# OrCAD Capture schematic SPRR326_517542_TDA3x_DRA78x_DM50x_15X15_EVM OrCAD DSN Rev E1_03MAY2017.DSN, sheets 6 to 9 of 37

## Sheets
6 SH07 - DDR3: size C; rev: E
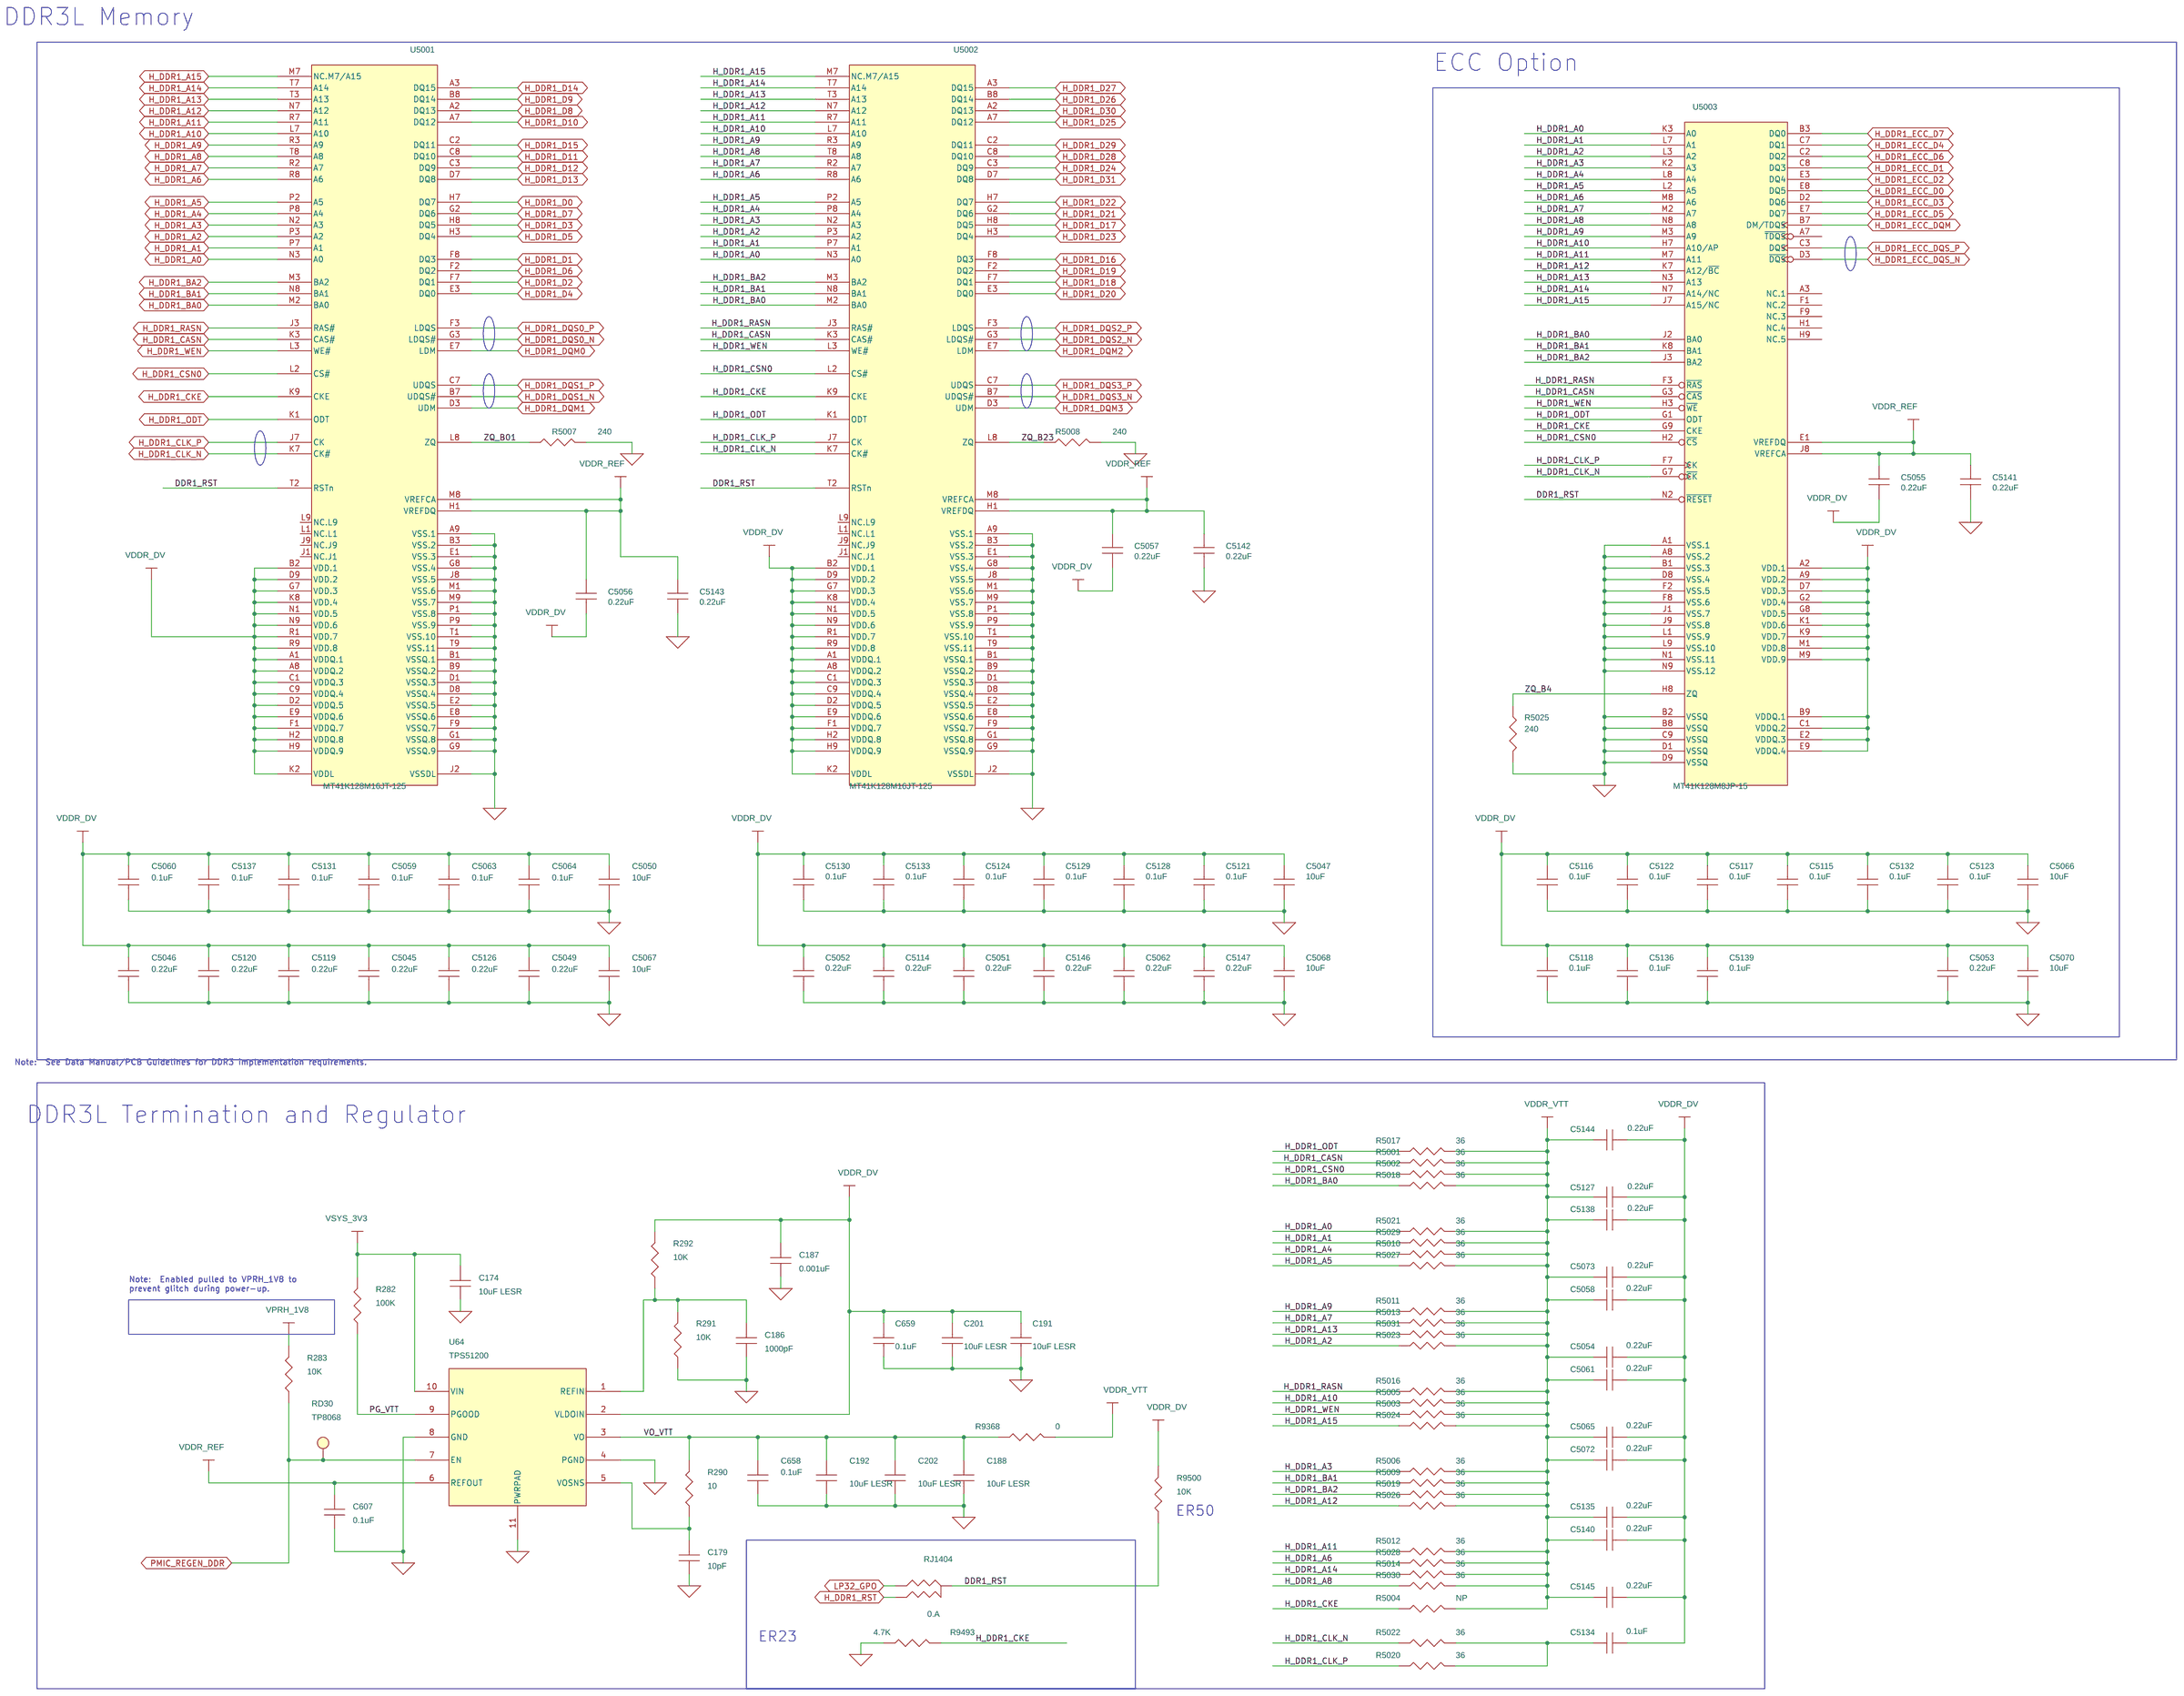
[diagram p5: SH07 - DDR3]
7 SH08 - VISIBILITY: size C; rev: D
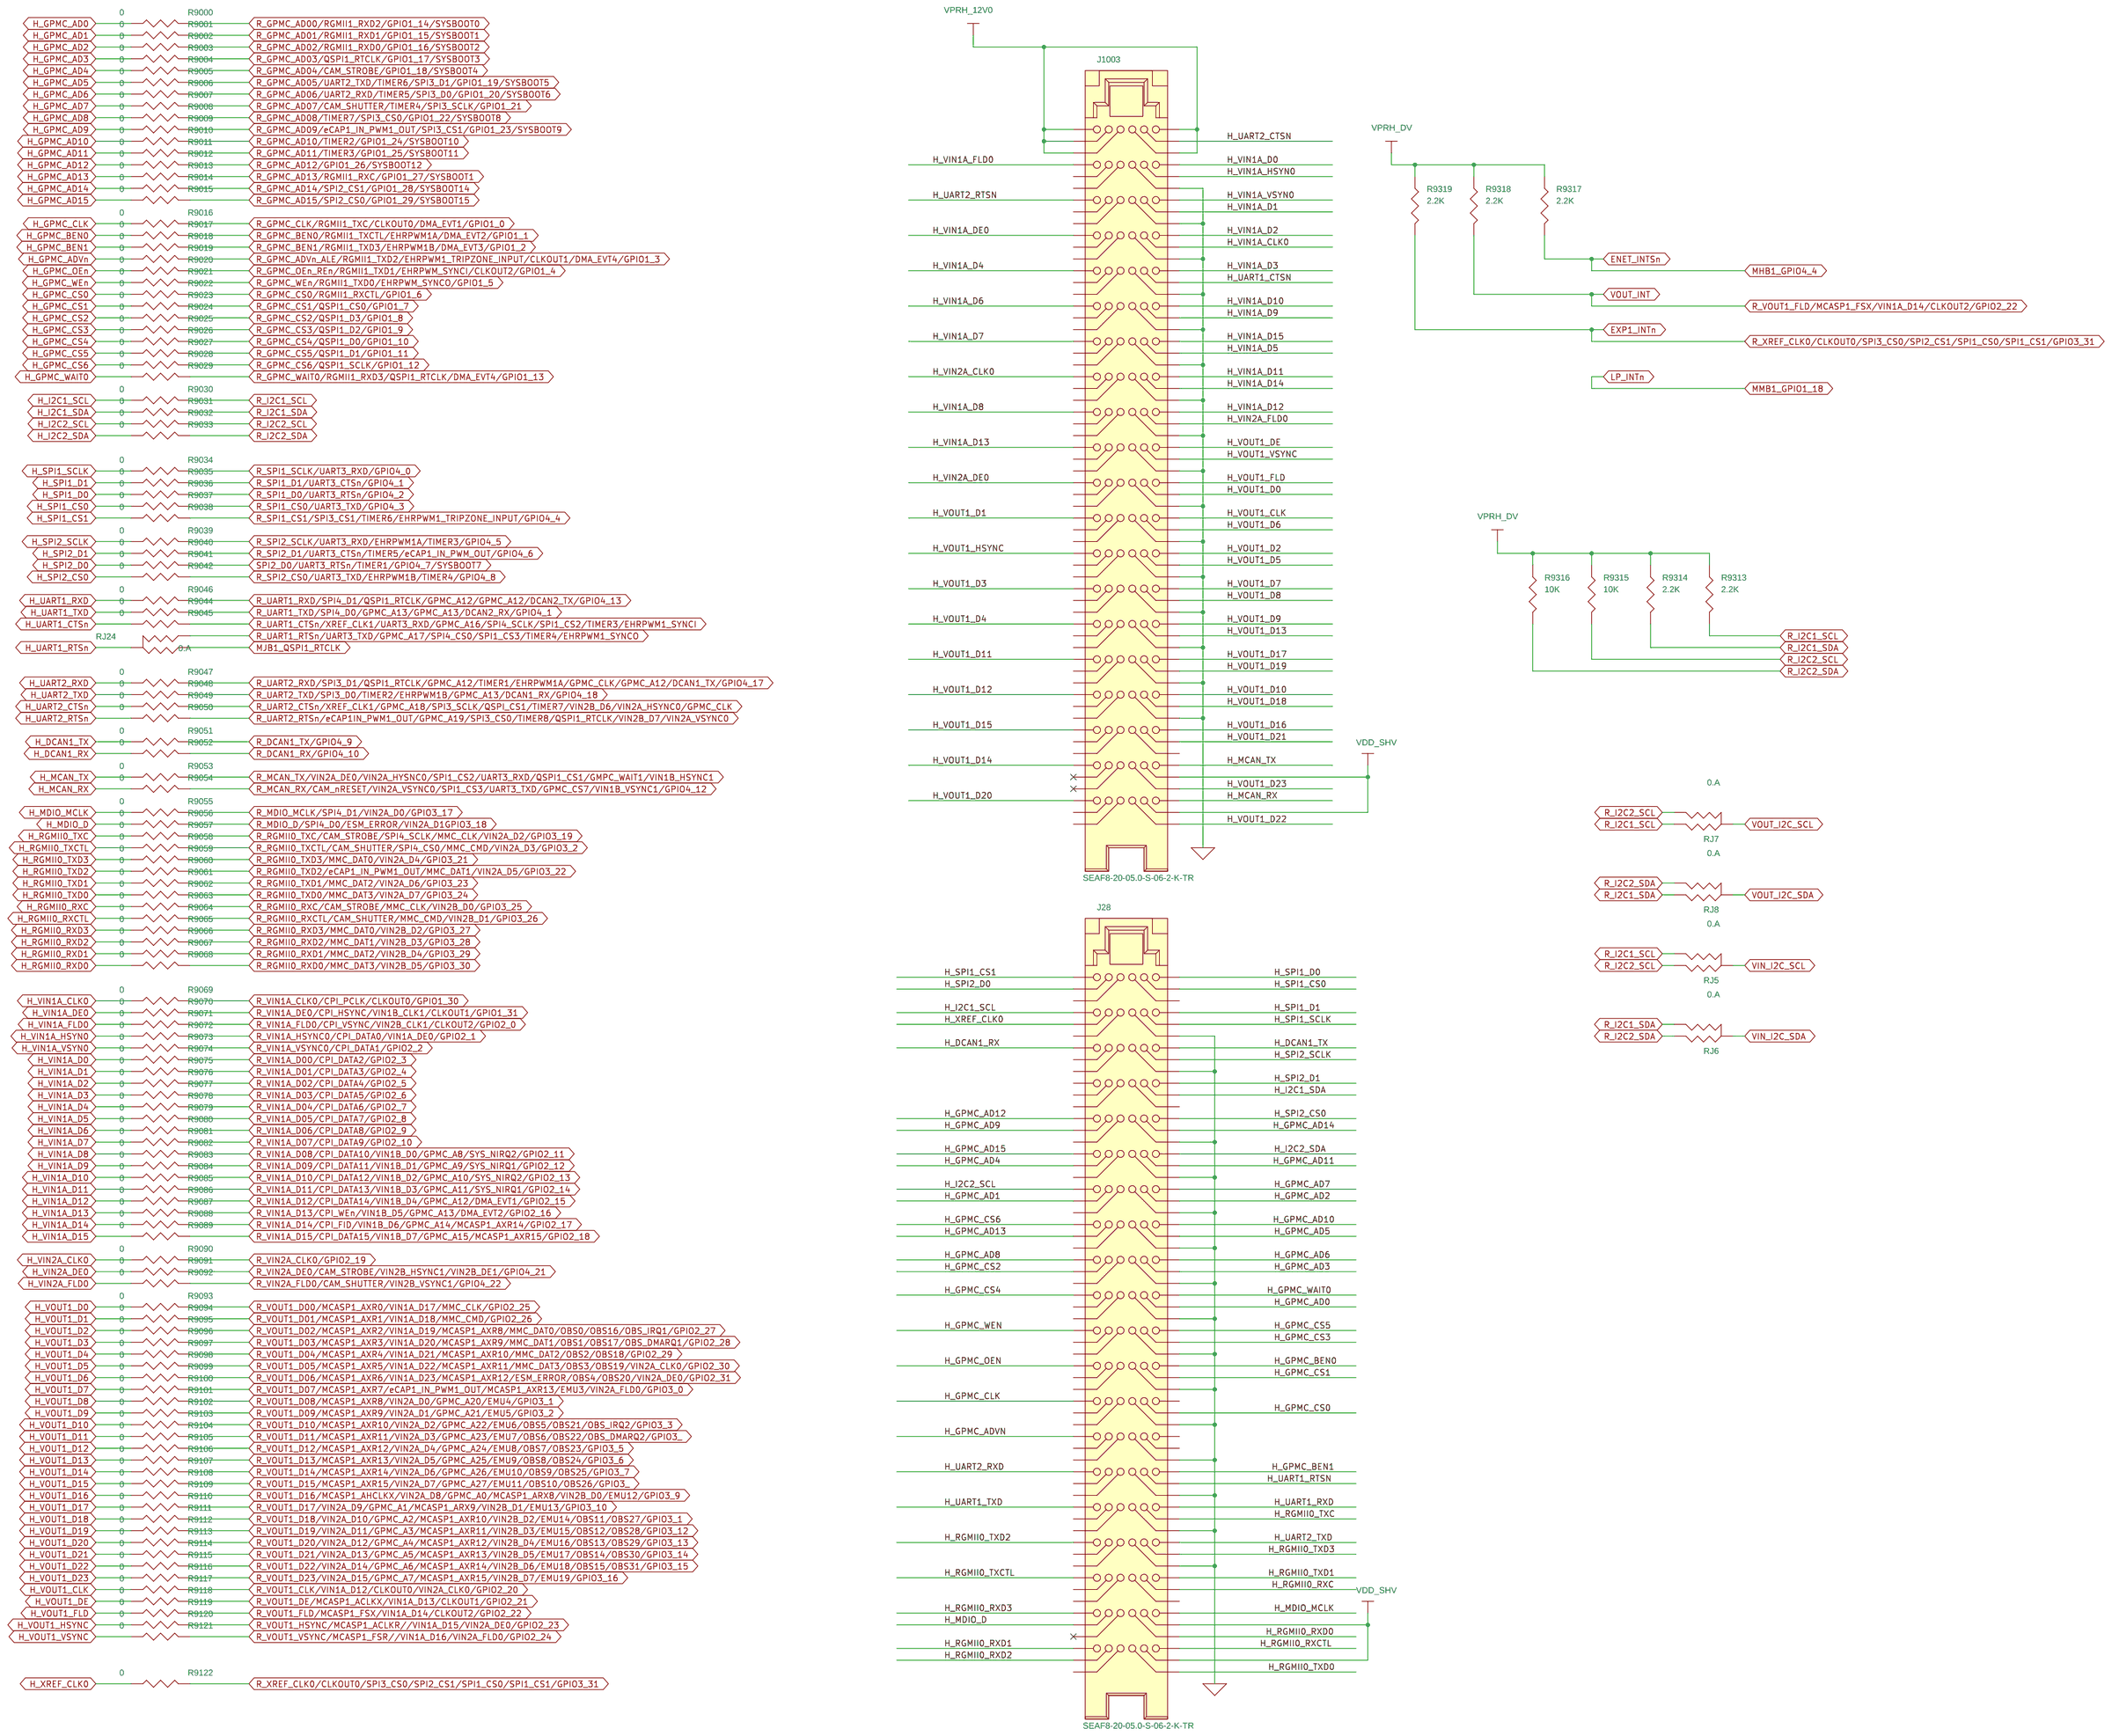
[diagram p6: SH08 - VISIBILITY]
8 SH10 - I2C EXPANDER: size C
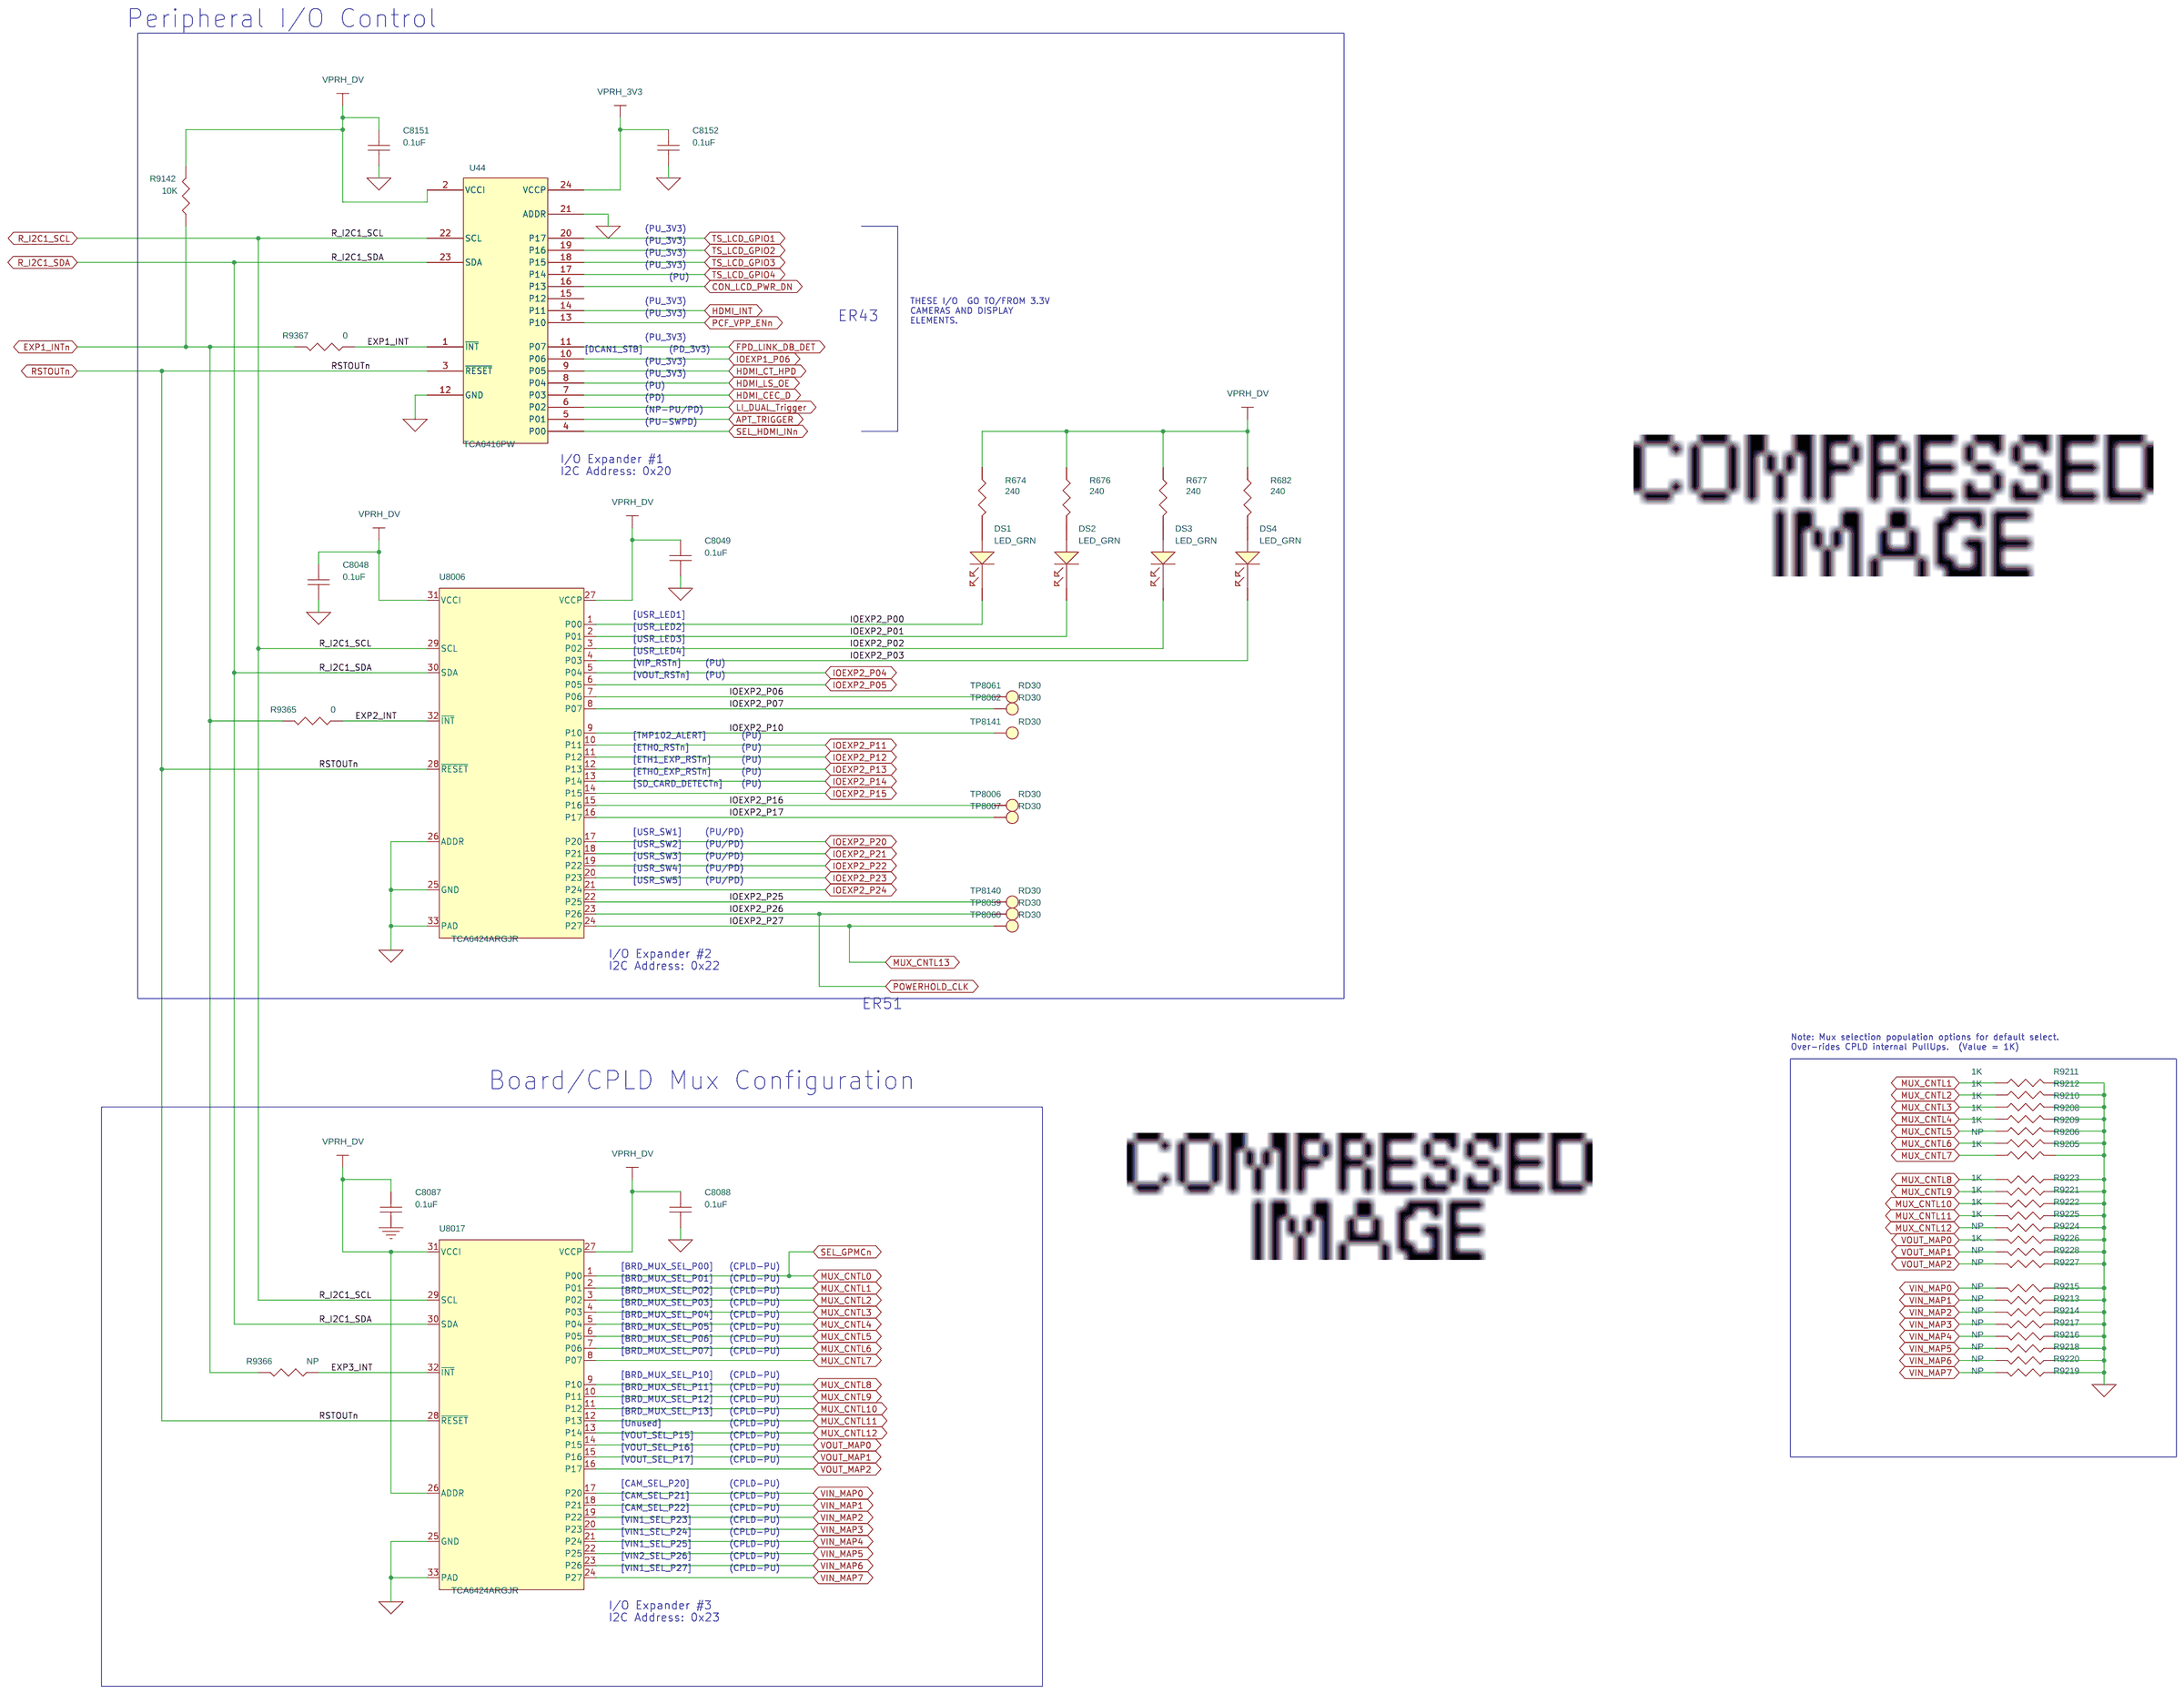
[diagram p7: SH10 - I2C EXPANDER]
9 SH15 - MEM NONVOLATILE: size C; rev: D
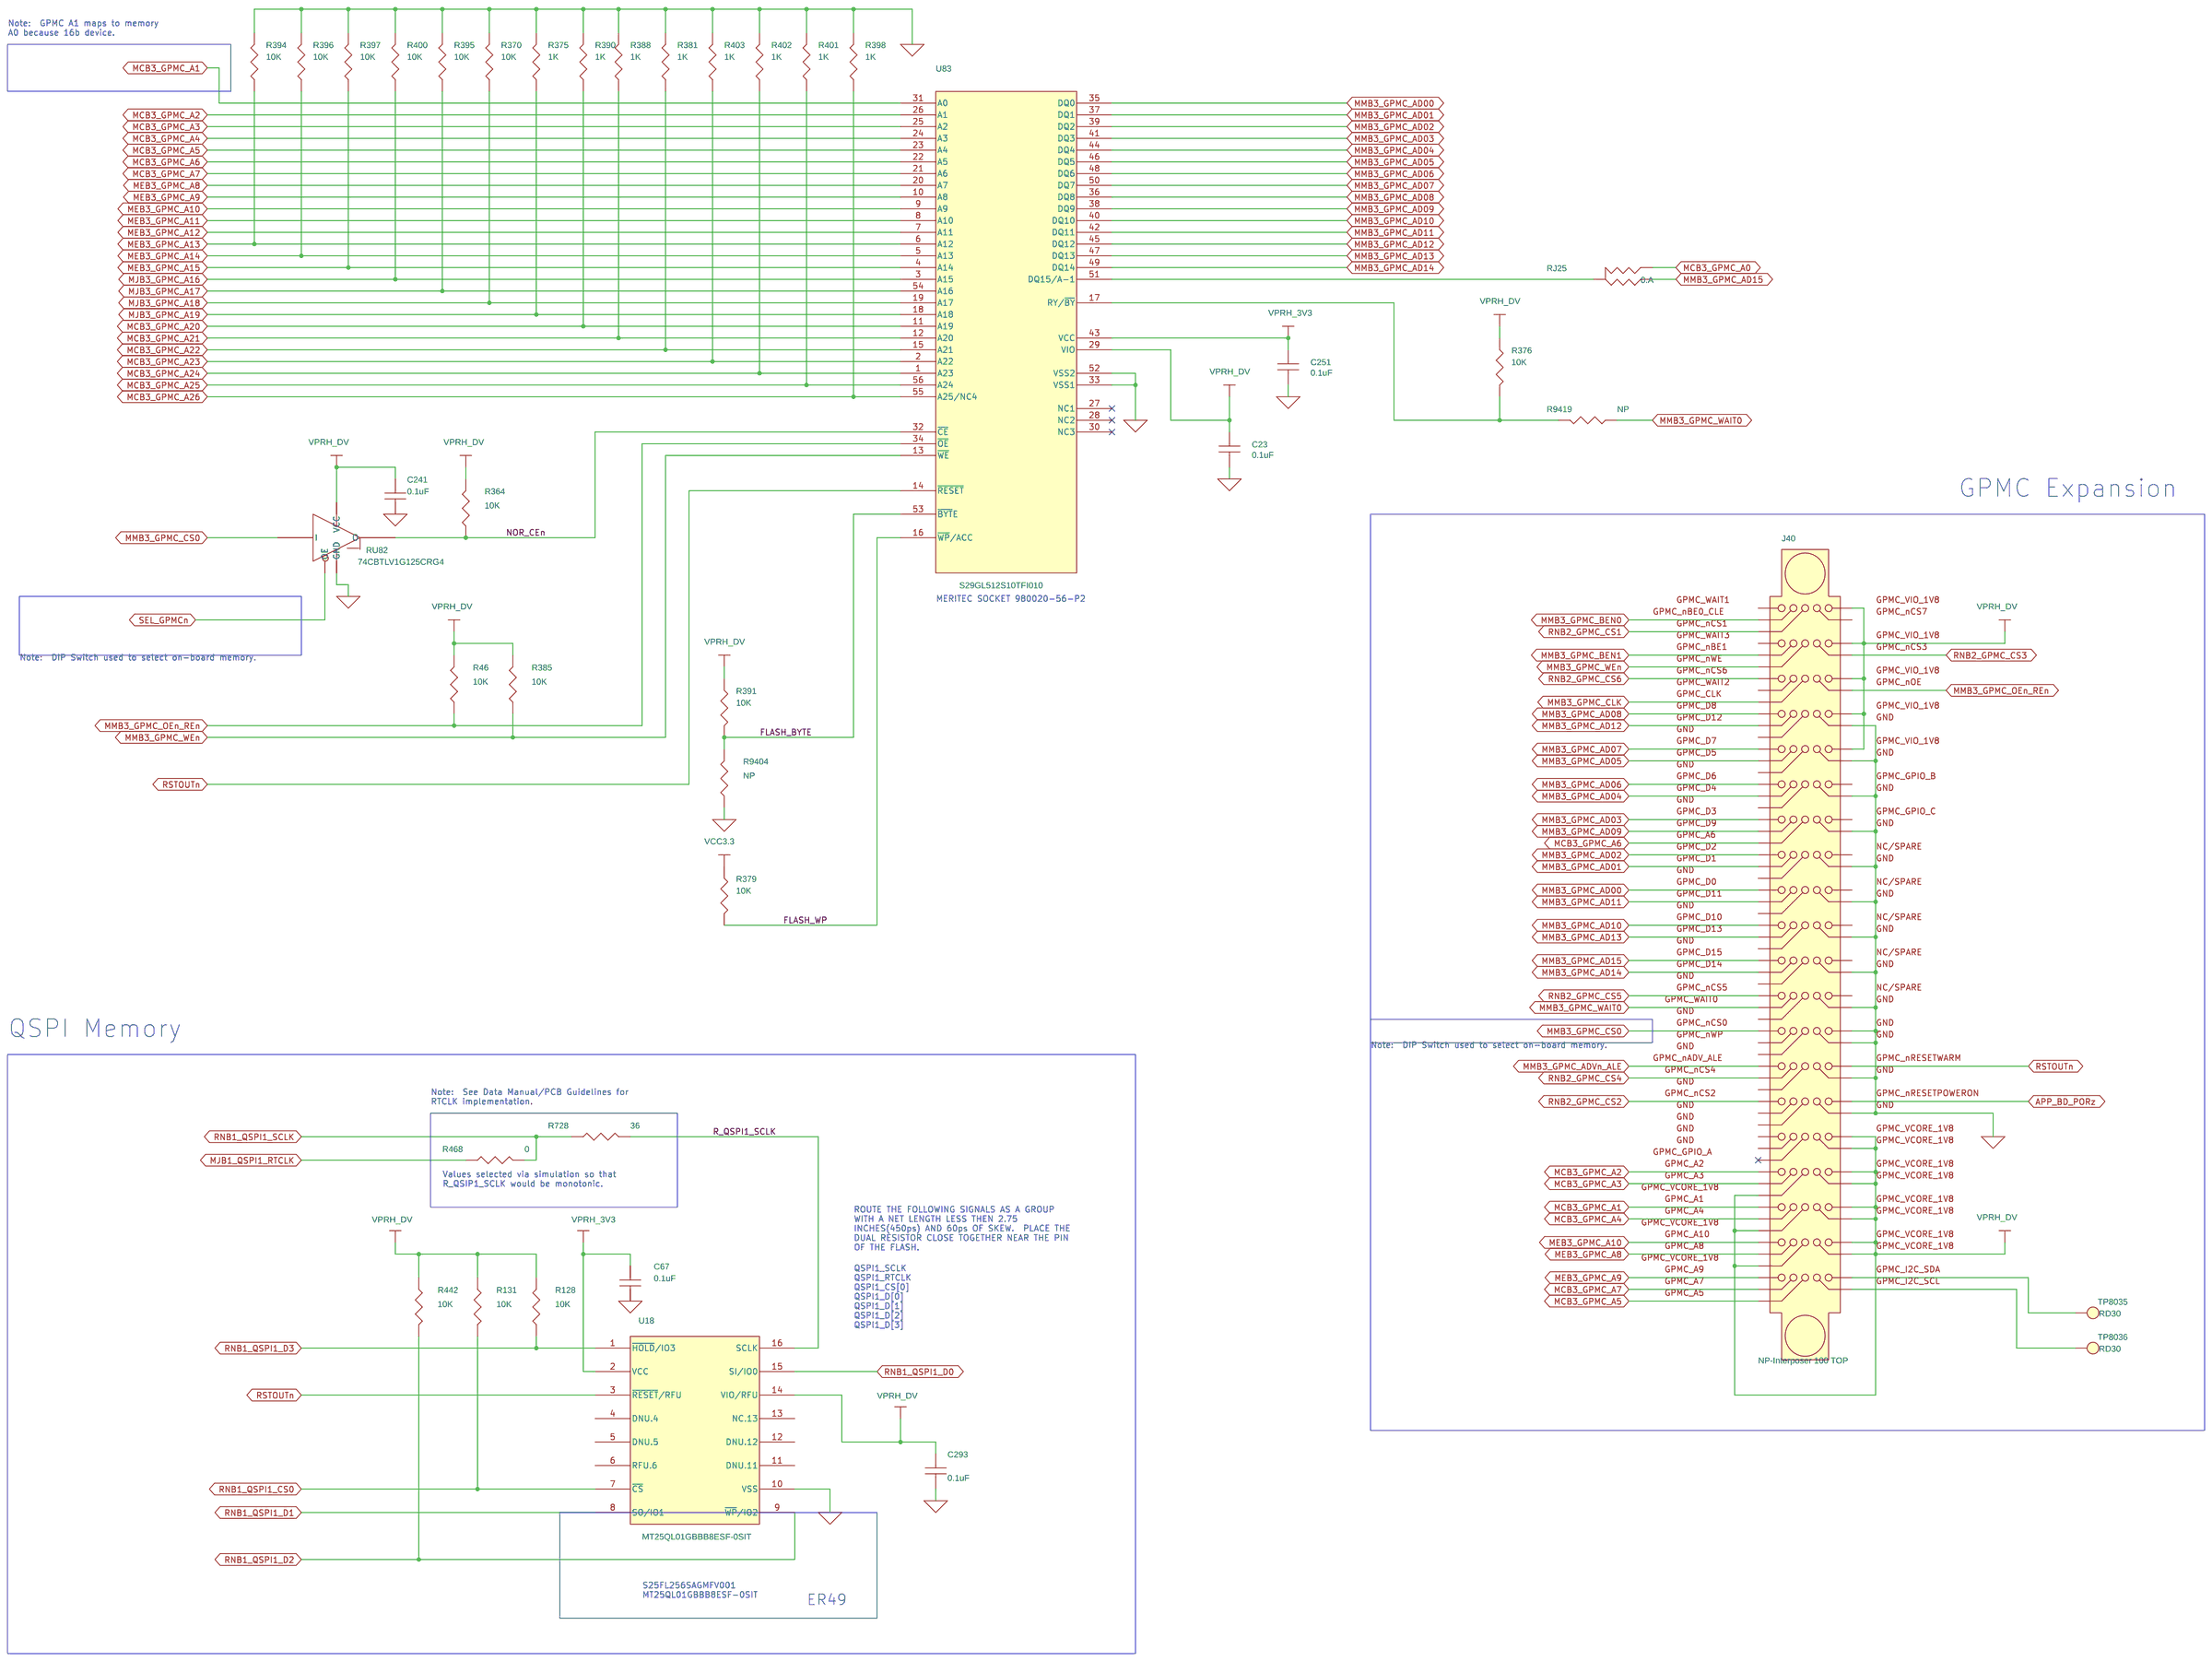
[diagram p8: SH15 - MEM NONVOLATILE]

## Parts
sheet SH07 - DDR3
C174  10uF LESR  [C1206-40X70]
C179  10pF  [c402-25]
C186  1000pF  [c402-25]
C187  0.001uF  [c402-25]
C188  10uF LESR  [C1206-40X70]
C191  10uF LESR  [C1206-40X70]
C192  10uF LESR  [C1206-40X70]
C201  10uF LESR  [C1206-40X70]
C202  10uF LESR  [C1206-40X70]
C607  0.1uF  [c402-25]
C658  0.1uF  [c402-25]
C659  0.1uF  [c402-25]
C5045  0.22uF  [c603-35x45]
C5046  0.22uF  [c603-35x45]
C5047  10uF  [c805-35x60]
C5049  0.22uF  [c603-35x45]
C5050  10uF  [c805-35x60]
C5051  0.22uF  [c603-35x45]
C5052  0.22uF  [c603-35x45]
C5053  0.22uF  [c603-35x45]
C5054  0.22uF  [c603-35x45]
C5055  0.22uF  [c603-35x45]
C5056  0.22uF  [c603-35x45]
C5057  0.22uF  [c603-35x45]
C5058  0.22uF  [c603-35x45]
C5059  0.1uF  [c402-25rd]
C5060  0.1uF  [c402-25rd]
C5061  0.22uF  [c603-35x45]
C5062  0.22uF  [c603-35x45]
C5063  0.1uF  [c402-25rd]
C5064  0.1uF  [c402-25rd]
C5065  0.22uF  [c603-35x45]
C5066  10uF  [c805-35x60]
C5067  10uF  [c805-35x60]
C5068  10uF  [c805-35x60]
C5070  10uF  [c805-35x60]
C5072  0.22uF  [c603-35x45]
C5073  0.22uF  [c603-35x45]
C5114  0.22uF  [c603-35x45]
C5115  0.1uF  [c402-25rd]
C5116  0.1uF  [c402-25rd]
C5117  0.1uF  [c402-25rd]
C5118  0.1uF  [c402-25rd]
C5119  0.22uF  [c603-35x45]
C5120  0.22uF  [c603-35x45]
C5121  0.1uF  [c402-25rd]
C5122  0.1uF  [c402-25rd]
C5123  0.1uF  [c402-25rd]
C5124  0.1uF  [c402-25rd]
C5126  0.22uF  [c603-35x45]
C5127  0.22uF  [c603-35x45]
C5128  0.1uF  [c402-25rd]
C5129  0.1uF  [c402-25rd]
C5130  0.1uF  [c402-25rd]
C5131  0.1uF  [c402-25rd]
C5132  0.1uF  [c402-25rd]
C5133  0.1uF  [c402-25rd]
C5134  0.1uF  [c402-25rd]
C5135  0.22uF  [c603-35x45]
C5136  0.1uF  [c402-25rd]
C5137  0.1uF  [c402-25rd]
C5138  0.22uF  [c603-35x45]
C5139  0.1uF  [c402-25rd]
C5140  0.22uF  [c603-35x45]
C5141  0.22uF  [c603-35x45]
C5142  0.22uF  [c603-35x45]
C5143  0.22uF  [c603-35x45]
C5144  0.22uF  [c603-35x45]
C5145  0.22uF  [c603-35x45]
C5146  0.22uF  [c603-35x45]
C5147  0.22uF  [c603-35x45]
R282  100K  [r402-25]
R283  10K  [r402-25]
R290  10  [r402-25]
R291  10K  [r402-25]
R292  10K  [r402-25]
R5001  36  [r402-25]
R5002  36  [r402-25]
R5003  36  [r402-25]
R5004  NP  [r402-25]
R5005  36  [r402-25]
R5006  36  [r402-25]
R5007  240  [r402-25]
R5008  240  [r402-25]
R5009  36  [r402-25]
R5010  36  [r402-25]
R5011  36  [r402-25]
R5012  36  [r402-25]
R5013  36  [r402-25]
R5014  36  [r402-25]
R5016  36  [r402-25]
R5017  36  [r402-25]
R5018  36  [r402-25]
R5019  36  [r402-25]
R5020  36  [r402-25]
R5021  36  [r402-25]
R5022  36  [r402-25]
R5023  36  [r402-25]
R5024  36  [r402-25]
R5025  240  [r402-25]
R5026  36  [r402-25]
R5027  36  [r402-25]
R5028  36  [r402-25]
R5029  36  [r402-25]
R5030  36  [r402-25]
R5031  36  [r402-25]
R9368  0  [r603-35x45]
R9493  4.7K  [r402-25]
R9500  10K  [r402-25]
RJ1404  0.A  [JMP402-25]
TP8068  RD30  [tp-30RD13]
U64  TPS51200  [drc10-11x33]
U5001  MT41K128M16JT-125  [intbga6x16-p8-re-pkg]
U5002  MT41K128M16JT-125  [intbga6x16-p8-re-pkg]
U5003  MT41K128M8JP-15  [intbga6x13-p8-ra-pkg]
sheet SH08 - VISIBILITY
J28  SEAF8-20-05.0-S-06-2-K-TR  [ti-jfs_seaf8-6x20pts_01]
J1003  SEAF8-20-05.0-S-06-2-K-TR  [ti-jfs_seaf8-6x20pts_01]
R9000  0  [r201-6p6spc]
R9001  0  [r201-6p6spc]
R9002  0  [r201-6p6spc]
R9003  0  [r201-6p6spc]
R9004  0  [r201-6p6spc]
R9005  0  [r201-6p6spc]
R9006  0  [r201-6p6spc]
R9007  0  [r201-6p6spc]
R9008  0  [r201-6p6spc]
R9009  0  [r201-6p6spc]
R9010  0  [r201-6p6spc]
R9011  0  [r201-6p6spc]
R9012  0  [r201-6p6spc]
R9013  0  [r201-6p6spc]
R9014  0  [r201-6p6spc]
R9015  0  [r201-6p6spc]
R9016  0  [r201-6p6spc]
R9017  0  [r201-6p6spc]
R9018  0  [r201-6p6spc]
R9019  0  [r201-6p6spc]
R9020  0  [r201-6p6spc]
R9021  0  [r201-6p6spc]
R9022  0  [r201-6p6spc]
R9023  0  [r201-6p6spc]
R9024  0  [r201-6p6spc]
R9025  0  [r201-6p6spc]
R9026  0  [r201-6p6spc]
R9027  0  [r201-6p6spc]
R9028  0  [r201-6p6spc]
R9029  0  [r201-6p6spc]
R9030  0  [r201-6p6spc]
R9031  0  [r201-6p6spc]
R9032  0  [r201-6p6spc]
R9033  0  [r201-6p6spc]
R9034  0  [r201-6p6spc]
R9035  0  [r201-6p6spc]
R9036  0  [r201-6p6spc]
R9037  0  [r201-6p6spc]
R9038  0  [r201-6p6spc]
R9039  0  [r201-6p6spc]
R9040  0  [r201-6p6spc]
R9041  0  [r201-6p6spc]
R9042  0  [r201-6p6spc]
R9044  0  [r201-6p6spc]
R9045  0  [r201-6p6spc]
R9046  0  [r201-6p6spc]
R9047  0  [r201-6p6spc]
R9048  0  [r201-6p6spc]
R9049  0  [r201-6p6spc]
R9050  0  [r201-6p6spc]
R9051  0  [r201-6p6spc]
R9052  0  [r201-6p6spc]
R9053  0  [r201-6p6spc]
R9054  0  [r201-6p6spc]
R9055  0  [r201-6p6spc]
R9056  0  [r201-6p6spc]
R9057  0  [r201-6p6spc]
R9058  0  [r201-6p6spc]
R9059  0  [r201-6p6spc]
R9060  0  [r201-6p6spc]
R9061  0  [r201-6p6spc]
R9062  0  [r201-6p6spc]
R9063  0  [r201-6p6spc]
R9064  0  [r201-6p6spc]
R9065  0  [r201-6p6spc]
R9066  0  [r201-6p6spc]
R9067  0  [r201-6p6spc]
R9068  0  [r201-6p6spc]
R9069  0  [r201-6p6spc]
R9070  0  [r201-6p6spc]
R9071  0  [r201-6p6spc]
R9072  0  [r201-6p6spc]
R9073  0  [r201-6p6spc]
R9074  0  [r201-6p6spc]
R9075  0  [r201-6p6spc]
R9076  0  [r201-6p6spc]
R9077  0  [r201-6p6spc]
R9078  0  [r201-6p6spc]
R9079  0  [r201-6p6spc]
R9080  0  [r201-6p6spc]
R9081  0  [r201-6p6spc]
R9082  0  [r201-6p6spc]
R9083  0  [r201-6p6spc]
R9084  0  [r201-6p6spc]
R9085  0  [r201-6p6spc]
R9086  0  [r201-6p6spc]
R9087  0  [r201-6p6spc]
R9088  0  [r201-6p6spc]
R9089  0  [r201-6p6spc]
R9090  0  [r201-6p6spc]
R9091  0  [r201-6p6spc]
R9092  0  [r201-6p6spc]
R9093  0  [r201-6p6spc]
R9094  0  [r201-6p6spc]
R9095  0  [r201-6p6spc]
R9096  0  [r201-6p6spc]
R9097  0  [r201-6p6spc]
R9098  0  [r201-6p6spc]
R9099  0  [r201-6p6spc]
R9100  0  [r201-6p6spc]
R9101  0  [r201-6p6spc]
R9102  0  [r201-6p6spc]
R9103  0  [r201-6p6spc]
R9104  0  [r201-6p6spc]
R9105  0  [r201-6p6spc]
R9106  0  [r201-6p6spc]
R9107  0  [r201-6p6spc]
R9108  0  [r201-6p6spc]
R9109  0  [r201-6p6spc]
R9110  0  [r201-6p6spc]
R9111  0  [r201-6p6spc]
R9112  0  [r201-6p6spc]
R9113  0  [r201-6p6spc]
R9114  0  [r201-6p6spc]
R9115  0  [r201-6p6spc]
R9116  0  [r201-6p6spc]
R9117  0  [r201-6p6spc]
R9118  0  [r201-6p6spc]
R9119  0  [r201-6p6spc]
R9120  0  [r201-6p6spc]
R9121  0  [r201-6p6spc]
R9122  0  [r201-6p6spc]
R9313  2.2K  [r402-25]
R9314  2.2K  [r402-25]
R9315  10K  [r402-25]
R9316  10K  [r402-25]
R9317  2.2K  [r402-25]
R9318  2.2K  [r402-25]
R9319  2.2K  [r402-25]
RJ5  0.A  [JMP402-25]
RJ6  0.A  [JMP402-25]
RJ7  0.A  [JMP402-25]
RJ8  0.A  [JMP402-25]
RJ24  0.A  [JMP402-25]
sheet SH10 - I2C EXPANDER
C8048  0.1uF  [c402-25]
C8049  0.1uF  [c402-25]
C8087  0.1uF  [c402-25]
C8088  0.1uF  [c402-25]
C8151  0.1uF  [c402-25]
C8152  0.1uF  [c402-25]
DS1  LED_GRN  [led1206-59x59]
DS2  LED_GRN  [led1206-59x59]
DS3  LED_GRN  [led1206-59x59]
DS4  LED_GRN  [led1206-59x59]
R674  240  [r402-25]
R676  240  [r402-25]
R677  240  [r402-25]
R682  240  [r402-25]
R9142  10K  [r402-25]
R9205  1K  [r402-25]
R9206  NP  [r402-25]
R9208  1K  [r402-25]
R9209  1K  [r402-25]
R9210  1K  [r402-25]
R9211  1K  [r402-25]
R9212  1K  [r402-25]
R9213  NP  [r402-25]
R9214  NP  [r402-25]
R9215  NP  [r402-25]
R9216  NP  [r402-25]
R9217  NP  [r402-25]
R9218  NP  [r402-25]
R9219  NP  [r402-25]
R9220  NP  [r402-25]
R9221  1K  [r402-25]
R9222  1K  [r402-25]
R9223  1K  [r402-25]
R9224  NP  [r402-25]
R9225  1K  [r402-25]
R9226  1K  [r402-25]
R9227  NP  [r402-25]
R9228  NP  [r402-25]
R9365  0  [r402-25]
R9366  NP  [r402-25]
R9367  0  [r402-25]
TP8006  RD30  [tp-30RD13]
TP8007  RD30  [tp-30RD13]
TP8059  RD30  [tp-30RD13]
TP8060  RD30  [tp-30RD13]
TP8061  RD30  [tp-30RD13]
TP8062  RD30  [tp-30RD13]
TP8140  RD30  [tp-30RD13]
TP8141  RD30  [tp-30RD13]
U44  TCA6416PW  [pw24-14x70]
U8006  TCA6424ARGJR  [cis_pvqfn-n32_01]
U8017  TCA6424ARGJR  [cis_pvqfn-n32_01]
sheet SH15 - MEM NONVOLATILE
C23  0.1uF  [c402-25]
C67  0.1uF  [c402-25]
C241  0.1uF  [c402-25]
C251  0.1uF  [c402-25]
C293  0.1uF  [c402-25]
J40  NP-Interposer 100 TOP  [ti-JMS_7170-020-GPMC_01]
R46  10K  [r402-25]
R128  10K  [r402-25]
R131  10K  [r402-25]
R364  10K  [r402-25]
R370  10K  [r402-25]
R375  1K  [r402-25]
R376  10K  [r402-25]
R379  10K  [r402-25]
R381  1K  [r402-25]
R385  10K  [r402-25]
R388  1K  [r402-25]
R390  1K  [r402-25]
R391  10K  [r402-25]
R394  10K  [r402-25]
R395  10K  [r402-25]
R396  10K  [r402-25]
R397  10K  [r402-25]
R398  1K  [r402-25]
R400  10K  [r402-25]
R401  1K  [r402-25]
R402  1K  [r402-25]
R403  1K  [r402-25]
R442  10K  [r402-25]
R468  0  [r402-25]
R728  36  [r402-25]
R9404  NP  [r402-25]
R9419  NP  [r402-25]
RJ25  0.A  [JMP402-25]
RU82  74CBTLV1G125CRG4  [dck-5]
TP8035  RD30  [tp-30RD13]
TP8036  RD30  [tp-30RD13]
U18  MT25QL01GBBB8ESF-0SIT  [so16-25x75-300]
U83  S29GL512S10TFI010  [x-s_tsop56_01]

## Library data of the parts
C174 C188 C191 C192 C201 C202 = CAP_NP: Part #: 101497-0101R
C179 = CAP_NP: Part #: 101782-1104R
C186 C187 = CAP_NP: Part #: 102058-1102R
C67 C293 C607 C658 C659 = CAP_NP: Part #: 104446-1100R
C5045 C5046 C5049 C5051-C5058 C5061 C5062 C5065 C5072 C5073 C5114 C5119 C5120 C5126 C5127 C5135 C5138 C5140-C5147 = CAP_AM_0603_0.22uf_x8l_16v_10_X: Part #: 103885-1220R
C5047 C5050 C5066-C5068 C5070 = CAP_AM_0805_10uf_x7r_10v_10_X: Part #: 104447-0101R
C5059 C5060 C5063 C5064 C5115-C5118 C5121-C5124 C5128-C5134 C5136 C5137 C5139 = CAP_AM_0402_0.1uf_x7r_16v_10%_X: Part #: 104446-1100R
R282 = R: Part #: 101370-1004R
R46 R283 R292 R364 R370 R376 R379 R385 R391 R394-R397 R400 R9315 R9316 R9500 = R: Part #: 101370-1003R
R290 = R: Part #: 101370-1000R
R291 = R: Part #: 102145-1003R
R5001-R5003 R5005 R5006 R5009-R5014 R5016-R5024 R5026-R5031 = RES_0402_49.9_1%_0.063W_X: Part #: 102145-3600R
R5004 = RES_0402_49.9_1%_0.063W_X: Part #: R0402-NOPOP
R5007 R5008 = R_0: Part #: 102145-2401R; SD PCB Footprint: EIA0402
R5025 = R: Part #: 102145-2401R
R9368 = R: Part #: 100687-0001R
R9493 = R: Part #: 101370-4702R
RJ5-RJ8 RJ24 RJ25 RJ1404 = RJUMP3: Part #: 101370-0001R
TP8006 TP8007 TP8035 TP8036 TP8059-TP8062 TP8068 TP8140 TP8141 = TESTPOINT: Part #: TP-30RD13-NO-POP
U64 = TPS51200: Part #: 103316-0001R
U5001 U5002 = DDR3_96BALL_X16_0: Part #: 104254-0012R
U5003 = EDJ1108DBSE_1: Part #: 104177-0125R
J28 J1003 = SEAF8-20-05.0-S-06-2-K-TR: Part #: 104455-2006R
R9000-R9042 R9044-R9122 = R_1: Part #: 103158-0001R
R9313 R9314 R9317-R9319 = R: Part #: 101370-2202R
C8048 C8049 C8087 C8088 C8151 C8152 = X5R_100nF_6V3: Part #: 104446-1100R
DS1-DS3 = LED_0_v2: Part #: 100823-0001R
DS4 = LED_RED_0: Part #: 100823-0001R
R674 R676 R677 R682 = R_0: Part #: 102145-2401R
R9142 = 0402_1%_010k: Part #: 101370-1003R
R9205 R9208-R9212 R9221-R9223 R9225 R9226 = R_1: Part #: 101370-1002R
R9206 R9213-R9220 R9224 R9227 R9228 R9366 = R_1: Part #: R0402-NOPOP
R9365 R9367 = R_1: Part #: 101370-0001R
U44 = TCA6416PW_2: Part #: 103163-0001R
U8006 U8017 = TCA6424A: Part #: 104230-0001R
C23 C251 = CAP_.1_uF_10%_0603: Part #: 104446-1100R
C241 = CAP_NP_2: Part #: 104446-1100R
J40 = Interposer_100_TOP_GPMC: GPAO_ART: 01100001034AA; Part #: NO-POP
R128 R131 R442 = RESISTOR: Part #: 101370-1003R
R375 R381 R388 R390 R398 R401-R403 = R: Part #: 101370-1002R
R468 = R: Part #: 101370-0001R
R728 = R: Part #: 102145-3600R
R9404 R9419 = R: Part #: R0402-NOPOP
RU82 = SN74LVC1G125: Part #: 101689-0125R
U18 = SPI_EEPROM_1: Part #: 104829-0001R
U83 = AM29LV256M_0: Part #: 104225-0100R

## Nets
GND: C23.2 C67.2 C174.1 C179.1 C186.1 C187.1 C188.1 C191.1 C192.1 C201.1 C202.1 C241.2 C251.2 C293.2 C607.1 C658.1 C659.1 C5045.2 C5046.2 C5047.2 C5049.2 C5050.2 C5051.2 C5052.2 C5053.2 C5059.2 C5060.2 C5062.2 C5063.2 C5064.2 C5066.2 C5067.2 C5068.2 C5070.2 C5114.2 C5115.2 C5116.2 C5117.2 C5118.2 C5119.2 C5120.2 C5121.2 C5122.2 C5123.2 C5124.2 C5126.2 C5128.2 C5129.2 C5130.2 C5131.2 C5132.2 C5133.2 C5136.2 C5137.2 C5139.2 C5141.2 C5142.2 C5143.2 C5146.2 C5147.2 C8048.2 C8049.2 C8087.2 C8088.2 C8151.2 C8152.2 J28.10 J28.16 J28.28 J28.34 J28.40 J28.46 J28.52 J28.58 J28.64 J28.70 J28.76 J28.82 J28.88 J28.94 J28.100 J40.D4 J40.D5 J40.D6 J40.D7 J40.D8 J40.D9 J40.D10 J40.D11 J40.D12 J40.D13 J40.D14 J40.D15 J40.E13 J1003.10 J1003.16 J1003.22 J1003.28 J1003.34 J1003.40 J1003.46 J1003.52 J1003.58 J1003.64 J1003.70 J1003.76 J1003.82 J1003.88 J1003.94 J1003.100 R291.1 R370.1 R375.1 R381.1 R388.1 R390.1 R394.1 R395.1 R396.1 R397.1 R398.1 R400.1 R401.1 R402.1 R403.1 R5007.2 R5008.2 R5025.2 R9205.1 R9206.1 R9208.1 R9209.1 R9210.1 R9211.1 R9212.1 R9213.1 R9214.1 R9215.1 R9216.1 R9217.1 R9218.1 R9219.1 R9220.1 R9221.1 R9222.1 R9223.1 R9224.1 R9225.1 R9226.1 R9227.1 R9228.1 R9404.1 R9493.2 RU82.3(GND) U18.10(VSS) U44.12(GND) U44.21(ADDR) U64.4(PGND) U64.8(GND) U64.11(PWRPAD) U83.33(VSS1) U83.52(VSS2) U5001.A9(VSS.1) U5001.B1(VSSQ.1) U5001.B3(VSS.2) U5001.B9(VSSQ.2) U5001.D1(VSSQ.3) U5001.D8(VSSQ.4) U5001.E1(VSS.3) U5001.E2(VSSQ.5) U5001.E8(VSSQ.6) U5001.F9(VSSQ.7) U5001.G1(VSSQ.8) U5001.G8(VSS.4) U5001.G9(VSSQ.9) U5001.J2(VSSDL) U5001.J8(VSS.5) U5001.M1(VSS.6) U5001.M9(VSS.7) U5001.P1(VSS.8) U5001.P9(VSS.9) U5001.T1(VSS.10) U5001.T9(VSS.11) U5002.A9(VSS.1) U5002.B1(VSSQ.1) U5002.B3(VSS.2) U5002.B9(VSSQ.2) U5002.D1(VSSQ.3) U5002.D8(VSSQ.4) U5002.E1(VSS.3) U5002.E2(VSSQ.5) U5002.E8(VSSQ.6) U5002.F9(VSSQ.7) U5002.G1(VSSQ.8) U5002.G8(VSS.4) U5002.G9(VSSQ.9) U5002.J2(VSSDL) U5002.J8(VSS.5) U5002.M1(VSS.6) U5002.M9(VSS.7) U5002.P1(VSS.8) U5002.P9(VSS.9) U5002.T1(VSS.10) U5002.T9(VSS.11) U5003.A1(VSS.1) U5003.A8(VSS.2) U5003.B1(VSS.3) U5003.B2(VSSQ) U5003.B8(VSSQ) U5003.C9(VSSQ) U5003.D1(VSSQ) U5003.D8(VSS.4) U5003.D9(VSSQ) U5003.F2(VSS.5) U5003.F8(VSS.6) U5003.J1(VSS.7) U5003.J9(VSS.8) U5003.L1(VSS.9) U5003.L9(VSS.10) U5003.N1(VSS.11) U5003.N9(VSS.12) U8006.25(GND) U8006.26(ADDR) U8006.33(PAD) U8017.25(GND) U8017.33(PAD) ; also on sheet 4 5 10 11 12 13 14 15 16 17 18 19 20 21 22 23 25 26 27 28 29 30 31 32 34 35 36 37
R_MCAN_TX/VIN2A_DE0/VIN2A_HYSNC0/SPI1_CS2/UART3_RXD/QSPI1_CS1/GMPC_WAIT1/VIN1B_HSYNC1: R9053.1 ; also on sheet 27
R_MDIO_D/SPI4_D0/ESM_ERROR/VIN2A_D1GPIO3_18: R9056.1 ; also on sheet 34
R_UART2_RTSn/eCAP1IN_PWM1_OUT/GPMC_A19/SPI3_CS0/TIMER8/QSPI1_RTCLK/VIN2B_D7/VIN2A_VSYNC0: R9050.1 ; also on sheet 32
VDD_SHV: J28.113 J28.119 J1003.113 J1003.119 ; also on sheet 5 15
VDDR_DV: C187.2 C191.2 C201.2 C659.2 C5045.1 C5046.1 C5047.1 C5049.1 C5050.1 C5051.1 C5052.1 C5053.1 C5054.2 C5055.2 C5056.2 C5057.2 C5058.2 C5059.1 C5060.1 C5061.2 C5062.1 C5063.1 C5064.1 C5065.2 C5066.1 C5067.1 C5068.1 C5070.1 C5072.2 C5073.2 C5114.1 C5115.1 C5116.1 C5117.1 C5118.1 C5119.1 C5120.1 C5121.1 C5122.1 C5123.1 C5124.1 C5126.1 C5127.2 C5128.1 C5129.1 C5130.1 C5131.1 C5132.1 C5133.1 C5134.2 C5135.2 C5136.1 C5137.1 C5138.2 C5139.1 C5140.2 C5144.2 C5145.2 C5146.1 C5147.1 R292.2 R9500.2 U64.2(VLDOIN) U5001.A1(VDDQ.1) U5001.A8(VDDQ.2) U5001.B2(VDD.1) U5001.C1(VDDQ.3) U5001.C9(VDDQ.4) U5001.D2(VDDQ.5) U5001.D9(VDD.2) U5001.E9(VDDQ.6) U5001.F1(VDDQ.7) U5001.G7(VDD.3) U5001.H2(VDDQ.8) U5001.H9(VDDQ.9) U5001.K2(VDDL) U5001.K8(VDD.4) U5001.N1(VDD.5) U5001.N9(VDD.6) U5001.R1(VDD.7) U5001.R9(VDD.8) U5002.A1(VDDQ.1) U5002.A8(VDDQ.2) U5002.B2(VDD.1) U5002.C1(VDDQ.3) U5002.C9(VDDQ.4) U5002.D2(VDDQ.5) U5002.D9(VDD.2) U5002.E9(VDDQ.6) U5002.F1(VDDQ.7) U5002.G7(VDD.3) U5002.H2(VDDQ.8) U5002.H9(VDDQ.9) U5002.K2(VDDL) U5002.K8(VDD.4) U5002.N1(VDD.5) U5002.N9(VDD.6) U5002.R1(VDD.7) U5002.R9(VDD.8) U5003.A2(VDD.1) U5003.A9(VDD.2) U5003.B9(VDDQ.1) U5003.C1(VDDQ.2) U5003.D7(VDD.3) U5003.E2(VDDQ.3) U5003.E9(VDDQ.4) U5003.G2(VDD.4) U5003.G8(VDD.5) U5003.K1(VDD.6) U5003.K9(VDD.7) U5003.M1(VDD.8) U5003.M9(VDD.9) ; also on sheet 37
VDDR_REF: C607.2 C5055.1 C5056.1 C5057.1 C5141.1 C5142.1 C5143.1 U64.6(REFOUT) U5001.H1(VREFDQ) U5001.M8(VREFCA) U5002.H1(VREFDQ) U5002.M8(VREFCA) U5003.E1(VREFDQ) U5003.J8(VREFCA)
VDDR_VTT: C5054.1 C5058.1 C5061.1 C5065.1 C5072.1 C5073.1 C5127.1 C5135.1 C5138.1 C5140.1 C5144.1 C5145.1 R5001.1 R5002.1 R5003.1 R5004.1 R5005.1 R5006.1 R5009.1 R5010.1 R5011.1 R5012.1 R5013.1 R5014.1 R5016.1 R5017.1 R5018.1 R5019.1 R5021.1 R5023.1 R5024.1 R5026.1 R5027.1 R5028.1 R5029.1 R5030.1 R5031.1 R9368.2
VIN_I2C_SCL: RJ5.2 ; also on sheet 21 22 31
VIN_I2C_SDA: RJ6.2 ; also on sheet 21 22 31
VIN_MAP0: R9215.2 U8017.17(P20) ; also on sheet 27
VIN_MAP1: R9213.2 U8017.18(P21) ; also on sheet 27
VIN_MAP2: R9214.2 U8017.19(P22) ; also on sheet 27
VIN_MAP3: R9217.2 U8017.20(P23) ; also on sheet 27
VIN_MAP4: R9216.2 U8017.21(P24) ; also on sheet 27
VIN_MAP5: R9218.2 U8017.22(P25) ; also on sheet 27
VIN_MAP6: R9220.2 U8017.23(P26) ; also on sheet 27
VIN_MAP7: R9219.2 U8017.24(P27) ; also on sheet 27
APP_BD_PORz: J40.E15 ; also on sheet 13
APT_TRIGGER: U44.5(P01) ; also on sheet 21
CON_LCD_PWR_DN: U44.16(P13) ; also on sheet 16
DDR1_RST: R9500.1 RJ1404.2 U5001.T2(RSTn) U5002.T2(RSTn) U5003.N2(~{RESET})
ENET_INTSn: R9317.2 ; also on sheet 11 34
EXP1_INT: R9367.2 U44.1(~{INT})
EXP1_INTn: R9122.1 R9142.1 R9319.2 R9365.1 R9366.1 R9367.1
EXP2_INT: R9365.2 U8006.32(~{INT})
EXP3_INT: R9366.2 U8017.32(~{INT})
FLASH_BYTE: R391.2 R9404.2 U83.53(~{BYT}E)
FLASH_WP: R379.2 U83.16(~{WP}/ACC)
FPD_LINK_DB_DET: U44.11(P07) ; also on sheet 21
H_DCAN1_RX: J28.13 R9052.2 ; also on sheet 3
H_DCAN1_TX: J28.18 R9051.2 ; also on sheet 3
H_DDR1_A0: R5021.2 U5001.N3(A0) U5002.N3(A0) U5003.K3(A0) ; also on sheet 3
H_DDR1_A1: R5029.2 U5001.P7(A1) U5002.P7(A1) U5003.L7(A1) ; also on sheet 3
H_DDR1_A2: R5023.2 U5001.P3(A2) U5002.P3(A2) U5003.L3(A2) ; also on sheet 3
H_DDR1_A3: R5006.2 U5001.N2(A3) U5002.N2(A3) U5003.K2(A3) ; also on sheet 3
H_DDR1_A4: R5010.2 U5001.P8(A4) U5002.P8(A4) U5003.L8(A4) ; also on sheet 3
H_DDR1_A5: R5027.2 U5001.P2(A5) U5002.P2(A5) U5003.L2(A5) ; also on sheet 3
H_DDR1_A6: R5028.2 U5001.R8(A6) U5002.R8(A6) U5003.M8(A6) ; also on sheet 3
H_DDR1_A7: R5013.2 U5001.R2(A7) U5002.R2(A7) U5003.M2(A7) ; also on sheet 3
H_DDR1_A8: R5030.2 U5001.T8(A8) U5002.T8(A8) U5003.N8(A8) ; also on sheet 3
H_DDR1_A9: R5011.2 U5001.R3(A9) U5002.R3(A9) U5003.M3(A9) ; also on sheet 3
H_DDR1_A10: R5005.2 U5001.L7(A10) U5002.L7(A10) U5003.H7(A10/AP) ; also on sheet 3
H_DDR1_A11: R5012.2 U5001.R7(A11) U5002.R7(A11) U5003.M7(A11) ; also on sheet 3
H_DDR1_A12: R5026.2 U5001.N7(A12) U5002.N7(A12) U5003.K7(A12/~{BC}) ; also on sheet 3
H_DDR1_A13: R5031.2 U5001.T3(A13) U5002.T3(A13) U5003.N3(A13) ; also on sheet 3
H_DDR1_A14: R5014.2 U5001.T7(A14) U5002.T7(A14) U5003.N7(A14/NC) ; also on sheet 3
H_DDR1_A15: R5024.2 U5001.M7(NC.M7/A15) U5002.M7(NC.M7/A15) U5003.J7(A15/NC) ; also on sheet 3
H_DDR1_BA0: R5018.2 U5001.M2(BA0) U5002.M2(BA0) U5003.J2(BA0) ; also on sheet 3
H_DDR1_BA1: R5009.2 U5001.N8(BA1) U5002.N8(BA1) U5003.K8(BA1) ; also on sheet 3
H_DDR1_BA2: R5019.2 U5001.M3(BA2) U5002.M3(BA2) U5003.J3(BA2) ; also on sheet 3
H_DDR1_CASN: R5001.2 U5001.K3(CAS#) U5002.K3(CAS#) U5003.G3(~{CAS}) ; also on sheet 3
H_DDR1_CKE: R5004.2 R9493.1 U5001.K9(CKE) U5002.K9(CKE) U5003.G9(CKE) ; also on sheet 3
H_DDR1_CLK_N: R5022.2 U5001.K7(CK#) U5002.K7(CK#) U5003.G7(~{CK}) ; also on sheet 3
H_DDR1_CLK_P: R5020.2 U5001.J7(CK) U5002.J7(CK) U5003.F7(CK) ; also on sheet 3
H_DDR1_CSN0: R5002.2 U5001.L2(CS#) U5002.L2(CS#) U5003.H2(~{CS}) ; also on sheet 3
H_DDR1_D0: U5001.H7(DQ7) ; also on sheet 3
H_DDR1_D1: U5001.F8(DQ3) ; also on sheet 3
H_DDR1_D2: U5001.F7(DQ1) ; also on sheet 3
H_DDR1_D3: U5001.H8(DQ5) ; also on sheet 3
H_DDR1_D4: U5001.E3(DQ0) ; also on sheet 3
H_DDR1_D5: U5001.H3(DQ4) ; also on sheet 3
H_DDR1_D6: U5001.F2(DQ2) ; also on sheet 3
H_DDR1_D7: U5001.G2(DQ6) ; also on sheet 3
H_DDR1_D8: U5001.A2(DQ13) ; also on sheet 3
H_DDR1_D9: U5001.B8(DQ14) ; also on sheet 3
H_DDR1_D10: U5001.A7(DQ12) ; also on sheet 3
H_DDR1_D11: U5001.C8(DQ10) ; also on sheet 3
H_DDR1_D12: U5001.C3(DQ9) ; also on sheet 3
H_DDR1_D13: U5001.D7(DQ8) ; also on sheet 3
H_DDR1_D14: U5001.A3(DQ15) ; also on sheet 3
H_DDR1_D15: U5001.C2(DQ11) ; also on sheet 3
H_DDR1_D16: U5002.F8(DQ3) ; also on sheet 3
H_DDR1_D17: U5002.H8(DQ5) ; also on sheet 3
H_DDR1_D18: U5002.F7(DQ1) ; also on sheet 3
H_DDR1_D19: U5002.F2(DQ2) ; also on sheet 3
H_DDR1_D20: U5002.E3(DQ0) ; also on sheet 3
H_DDR1_D21: U5002.G2(DQ6) ; also on sheet 3
H_DDR1_D22: U5002.H7(DQ7) ; also on sheet 3
H_DDR1_D23: U5002.H3(DQ4) ; also on sheet 3
H_DDR1_D24: U5002.C3(DQ9) ; also on sheet 3
H_DDR1_D25: U5002.A7(DQ12) ; also on sheet 3
H_DDR1_D26: U5002.B8(DQ14) ; also on sheet 3
H_DDR1_D27: U5002.A3(DQ15) ; also on sheet 3
H_DDR1_D28: U5002.C8(DQ10) ; also on sheet 3
H_DDR1_D29: U5002.C2(DQ11) ; also on sheet 3
H_DDR1_D30: U5002.A2(DQ13) ; also on sheet 3
H_DDR1_D31: U5002.D7(DQ8) ; also on sheet 3
H_DDR1_DQM0: U5001.E7(LDM) ; also on sheet 3
H_DDR1_DQM1: U5001.D3(UDM) ; also on sheet 3
H_DDR1_DQM2: U5002.E7(LDM) ; also on sheet 3
H_DDR1_DQM3: U5002.D3(UDM) ; also on sheet 3
H_DDR1_DQS0_N: U5001.G3(LDQS#) ; also on sheet 3
H_DDR1_DQS0_P: U5001.F3(LDQS) ; also on sheet 3
H_DDR1_DQS1_N: U5001.B7(UDQS#) ; also on sheet 3
H_DDR1_DQS1_P: U5001.C7(UDQS) ; also on sheet 3
H_DDR1_DQS2_N: U5002.G3(LDQS#) ; also on sheet 3
H_DDR1_DQS2_P: U5002.F3(LDQS) ; also on sheet 3
H_DDR1_DQS3_N: U5002.B7(UDQS#) ; also on sheet 3
H_DDR1_DQS3_P: U5002.C7(UDQS) ; also on sheet 3
H_DDR1_ECC_D0: U5003.E8(DQ5) ; also on sheet 3
H_DDR1_ECC_D1: U5003.C8(DQ3) ; also on sheet 3
H_DDR1_ECC_D2: U5003.E3(DQ4) ; also on sheet 3
H_DDR1_ECC_D3: U5003.D2(DQ6) ; also on sheet 3
H_DDR1_ECC_D4: U5003.C7(DQ1) ; also on sheet 3
H_DDR1_ECC_D5: U5003.E7(DQ7) ; also on sheet 3
H_DDR1_ECC_D6: U5003.C2(DQ2) ; also on sheet 3
H_DDR1_ECC_D7: U5003.B3(DQ0) ; also on sheet 3
H_DDR1_ECC_DQM: U5003.B7(DM/TDQS) ; also on sheet 3
H_DDR1_ECC_DQS_N: U5003.D3(~{DQS}) ; also on sheet 3
H_DDR1_ECC_DQS_P: U5003.C3(DQS) ; also on sheet 3
H_DDR1_ODT: R5017.2 U5001.K1(ODT) U5002.K1(ODT) U5003.G1(ODT) ; also on sheet 3
H_DDR1_RASN: R5016.2 U5001.J3(RAS#) U5002.J3(RAS#) U5003.F3(~{RAS}) ; also on sheet 3
H_DDR1_RST: RJ1404.3 ; also on sheet 3
H_DDR1_WEN: R5003.2 U5001.L3(WE#) U5002.L3(WE#) U5003.H3(~{WE}) ; also on sheet 3
H_GPMC_AD0: J28.59 R9000.2 ; also on sheet 3
H_GPMC_AD1: J28.38 R9001.2 ; also on sheet 3
H_GPMC_AD2: J28.41 R9002.2 ; also on sheet 3
H_GPMC_AD3: J28.53 R9003.2 ; also on sheet 3
H_GPMC_AD4: J28.32 R9004.2 ; also on sheet 3
H_GPMC_AD5: J28.47 R9005.2 ; also on sheet 3
H_GPMC_AD6: J28.54 R9006.2 ; also on sheet 3
H_GPMC_AD7: J28.42 R9007.2 ; also on sheet 3
H_GPMC_AD8: J28.49 R9008.2 ; also on sheet 3
H_GPMC_AD9: J28.26 R9009.2 ; also on sheet 3
H_GPMC_AD10: J28.48 R9010.2 ; also on sheet 3
H_GPMC_AD11: J28.35 R9011.2 ; also on sheet 3
H_GPMC_AD12: J28.25 R9012.2 ; also on sheet 3
H_GPMC_AD13: J28.44 R9013.2 ; also on sheet 3
H_GPMC_AD14: J28.29 R9014.2 ; also on sheet 3
H_GPMC_AD15: J28.31 R9015.2 ; also on sheet 3
H_GPMC_ADVn: J28.79 R9019.2 ; also on sheet 3
H_GPMC_BEN0: J28.72 R9017.2 ; also on sheet 3
H_GPMC_BEN1: J28.90 R9018.2 ; also on sheet 3
H_GPMC_CLK: J28.73 R9016.2 ; also on sheet 3
H_GPMC_CS0: J28.77 R9022.2 ; also on sheet 3
H_GPMC_CS1: J28.71 R9023.2 ; also on sheet 3
H_GPMC_CS2: J28.50 R9024.2 ; also on sheet 3
H_GPMC_CS3: J28.65 R9025.2 ; also on sheet 3
H_GPMC_CS4: J28.55 R9026.2 ; also on sheet 3
H_GPMC_CS5: J28.66 R9027.2 ; also on sheet 3
H_GPMC_CS6: J28.43 R9028.2 ; also on sheet 3
H_GPMC_OEn: J28.67 R9020.2 ; also on sheet 3
H_GPMC_WAIT0: J28.60 R9029.2 ; also on sheet 3
H_GPMC_WEn: J28.61 R9021.2 ; also on sheet 3
H_I2C1_SCL: J28.7 R9030.2 ; also on sheet 3
H_I2C1_SDA: J28.23 R9031.2 ; also on sheet 3
H_I2C2_SCL: J28.37 R9032.2 ; also on sheet 3
H_I2C2_SDA: J28.36 R9033.2 ; also on sheet 3
H_MCAN_RX: J1003.120 R9054.2 ; also on sheet 3
H_MCAN_TX: J1003.114 R9053.2 ; also on sheet 3
H_MDIO_D: J28.110 R9056.2 ; also on sheet 3
H_MDIO_MCLK: J28.114 R9055.2 ; also on sheet 3
H_RGMII0_RXC: J28.107 R9063.2 ; also on sheet 3
H_RGMII0_RXCTL: J28.120 R9064.2 ; also on sheet 3
H_RGMII0_RXD0: J28.112 R9068.2 ; also on sheet 3
H_RGMII0_RXD1: J28.115 R9067.2 ; also on sheet 3
H_RGMII0_RXD2: J28.116 R9066.2 ; also on sheet 3
H_RGMII0_RXD3: J28.109 R9065.2 ; also on sheet 3
H_RGMII0_TXC: J28.95 R9057.2 ; also on sheet 3
H_RGMII0_TXCTL: J28.103 R9058.2 ; also on sheet 3
H_RGMII0_TXD0: J28.118 R9062.2 ; also on sheet 3
H_RGMII0_TXD1: J28.108 R9061.2 ; also on sheet 3
H_RGMII0_TXD2: J28.97 R9060.2 ; also on sheet 3
H_RGMII0_TXD3: J28.101 R9059.2 ; also on sheet 3
H_SPI1_CS0: J28.5 R9037.2 ; also on sheet 3
H_SPI1_CS1: J28.1 R9038.2 ; also on sheet 3
H_SPI1_D0: J28.6 R9036.2 ; also on sheet 3
H_SPI1_D1: J28.12 R9035.2 ; also on sheet 3
H_SPI1_SCLK: J28.11 R9034.2 ; also on sheet 3
H_SPI2_CS0: J28.30 R9042.2 ; also on sheet 3
H_SPI2_D0: J28.2 R9041.2 ; also on sheet 3
H_SPI2_D1: J28.24 R9040.2 ; also on sheet 3
H_SPI2_SCLK: J28.17 R9039.2 ; also on sheet 3
H_UART1_CTSn: J1003.29 R9045.2 ; also on sheet 3
H_UART1_RTSn: J28.89 RJ24.2 ; also on sheet 3
H_UART1_RXD: J28.96 R9046.2 ; also on sheet 3
H_UART1_TXD: J28.91 R9044.2 ; also on sheet 3
H_UART2_CTSn: J1003.5 R9049.2 ; also on sheet 3
H_UART2_RTSn: J1003.13 R9050.2 ; also on sheet 3
H_UART2_RXD: J28.85 R9047.2 ; also on sheet 3
H_UART2_TXD: J28.102 R9048.2 ; also on sheet 3
H_VIN1A_CLK0: J1003.23 R9069.2 ; also on sheet 4
H_VIN1A_D0: J1003.12 R9074.2 ; also on sheet 4
H_VIN1A_D1: J1003.17 R9075.2 ; also on sheet 4
H_VIN1A_D2: J1003.24 R9076.2 ; also on sheet 4
H_VIN1A_D3: J1003.30 R9077.2 ; also on sheet 4
H_VIN1A_D4: J1003.25 R9078.2 ; also on sheet 4
H_VIN1A_D5: J1003.41 R9079.2 ; also on sheet 4
H_VIN1A_D6: J1003.31 R9080.2 ; also on sheet 4
H_VIN1A_D7: J1003.37 R9081.2 ; also on sheet 4
H_VIN1A_D8: J1003.49 R9082.2 ; also on sheet 4
H_VIN1A_D9: J1003.35 R9083.2 ; also on sheet 4
H_VIN1A_D10: J1003.36 R9084.2 ; also on sheet 4
H_VIN1A_D11: J1003.48 R9085.2 ; also on sheet 4
H_VIN1A_D12: J1003.54 R9086.2 ; also on sheet 4
H_VIN1A_D13: J1003.55 R9087.2 ; also on sheet 4
H_VIN1A_D14: J1003.47 R9088.2 ; also on sheet 4
H_VIN1A_D15: J1003.42 R9089.2 ; also on sheet 4
H_VIN1A_DE0: J1003.19 R9070.2 ; also on sheet 4
H_VIN1A_FLD0: J1003.7 R9071.2 ; also on sheet 4
H_VIN1A_HSYN0: J1003.11 R9072.2 ; also on sheet 4
H_VIN1A_VSYN0: J1003.18 R9073.2 ; also on sheet 4
H_VIN2A_CLK0: J1003.43 R9090.2 ; also on sheet 4
H_VIN2A_DE0: J1003.61 R9091.2 ; also on sheet 4
H_VIN2A_FLD0: J1003.53 R9092.2 ; also on sheet 4
H_VOUT1_CLK: J1003.72 R9117.2 ; also on sheet 4
H_VOUT1_D0: J1003.65 R9093.2 ; also on sheet 4
H_VOUT1_D1: J1003.67 R9094.2 ; also on sheet 4
H_VOUT1_D2: J1003.78 R9095.2 ; also on sheet 4
H_VOUT1_D3: J1003.79 R9096.2 ; also on sheet 4
H_VOUT1_D4: J1003.85 R9097.2 ; also on sheet 4
H_VOUT1_D5: J1003.77 R9098.2 ; also on sheet 4
H_VOUT1_D6: J1003.71 R9099.2 ; also on sheet 4
H_VOUT1_D7: J1003.84 R9100.2 ; also on sheet 4
H_VOUT1_D8: J1003.83 R9101.2 ; also on sheet 4
H_VOUT1_D9: J1003.90 R9102.2 ; also on sheet 4
H_VOUT1_D10: J1003.102 R9103.2 ; also on sheet 4
H_VOUT1_D11: J1003.91 R9104.2 ; also on sheet 4
H_VOUT1_D12: J1003.97 R9105.2 ; also on sheet 4
H_VOUT1_D13: J1003.89 R9106.2 ; also on sheet 4
H_VOUT1_D14: J1003.109 R9107.2 ; also on sheet 4
H_VOUT1_D15: J1003.103 R9108.2 ; also on sheet 4
H_VOUT1_D16: J1003.108 R9109.2 ; also on sheet 4
H_VOUT1_D17: J1003.96 R9110.2 ; also on sheet 4
H_VOUT1_D18: J1003.101 R9111.2 ; also on sheet 4
H_VOUT1_D19: J1003.95 R9112.2 ; also on sheet 4
H_VOUT1_D20: J1003.115 R9113.2 ; also on sheet 4
H_VOUT1_D21: J1003.107 R9114.2 ; also on sheet 4
H_VOUT1_D22: J1003.118 R9115.2 ; also on sheet 4
H_VOUT1_D23: J1003.112 R9116.2 ; also on sheet 4
H_VOUT1_DE: J1003.60 R9118.2 ; also on sheet 4
H_VOUT1_FLD: J1003.66 R9119.2 ; also on sheet 4
H_VOUT1_HSYNC: J1003.73 R9120.2 ; also on sheet 4
H_VOUT1_VSYNC: J1003.59 R9121.2 ; also on sheet 4
H_XREF_CLK0: J28.8 R9122.2 ; also on sheet 4
HDMI_CEC_D: U44.7(P03) ; also on sheet 17
HDMI_CT_HPD: U44.9(P05) ; also on sheet 17
HDMI_INT: U44.14(P11) ; also on sheet 23
HDMI_LS_OE: U44.8(P04) ; also on sheet 17
IOEXP1_P06: U44.10(P06) ; also on sheet 35
IOEXP2_P00: DS1.1(cathode) U8006.1(P00)
IOEXP2_P01: DS2.1(cathode) U8006.2(P01)
IOEXP2_P02: DS3.1(cathode) U8006.3(P02)
IOEXP2_P03: DS4.1(cathode) U8006.4(P03)
IOEXP2_P04: U8006.5(P04) ; also on sheet 27
IOEXP2_P05: U8006.6(P05) ; also on sheet 26
IOEXP2_P06: TP8061.1(TP) U8006.7(P06)
IOEXP2_P07: TP8062.1(TP) U8006.8(P07)
IOEXP2_P10: TP8141.1(TP) U8006.9(P10)
IOEXP2_P11: U8006.10(P11) ; also on sheet 36
IOEXP2_P12: U8006.11(P12) ; also on sheet 11
IOEXP2_P13: U8006.12(P13) ; also on sheet 11
IOEXP2_P14: U8006.13(P14) ; also on sheet 11
IOEXP2_P15: U8006.14(P15) ; also on sheet 36
IOEXP2_P16: TP8006.1(TP) U8006.15(P16)
IOEXP2_P17: TP8007.1(TP) U8006.16(P17)
IOEXP2_P20: U8006.17(P20) ; also on sheet 27 31
IOEXP2_P21: U8006.18(P21) ; also on sheet 27 31
IOEXP2_P22: U8006.19(P22) ; also on sheet 26 31
IOEXP2_P23: U8006.20(P23) ; also on sheet 26 31
IOEXP2_P24: U8006.21(P24) ; also on sheet 26
IOEXP2_P25: TP8140.1(TP) U8006.22(P25)
LI_DUAL_Trigger: U44.6(P02) ; also on sheet 20
LP32_GPO: RJ1404.1 ; also on sheet 13
MCB3_GPMC_A0: RJ25.3 ; also on sheet 30
MCB3_GPMC_A1: J40.A18 U83.31(A0) ; also on sheet 30
MCB3_GPMC_A2: J40.A17 U83.26(A1) ; also on sheet 30
MCB3_GPMC_A3: J40.B17 U83.25(A2) ; also on sheet 30
MCB3_GPMC_A4: J40.B18 U83.24(A3) ; also on sheet 30
MCB3_GPMC_A5: J40.C20 U83.23(A4) ; also on sheet 30
MCB3_GPMC_A6: J40.C7 U83.22(A5) ; also on sheet 30
MCB3_GPMC_A7: J40.B20 U83.21(A6) ; also on sheet 30
MCB3_GPMC_A20: R390.2 U83.11(A19) ; also on sheet 30
MCB3_GPMC_A21: R388.2 U83.12(A20) ; also on sheet 30
MCB3_GPMC_A22: R381.2 U83.15(A21) ; also on sheet 30
MCB3_GPMC_A23: R403.2 U83.2(A22) ; also on sheet 30
MCB3_GPMC_A24: R402.2 U83.1(A23) ; also on sheet 30
MCB3_GPMC_A25: R401.2 U83.56(A24) ; also on sheet 30
MCB3_GPMC_A26: R398.2 U83.55(A25/NC4) ; also on sheet 30
MEB3_GPMC_A8: J40.B19 U83.20(A7) ; also on sheet 34
MEB3_GPMC_A9: J40.A20 U83.10(A8) ; also on sheet 34
MEB3_GPMC_A10: J40.A19 U83.9(A9) ; also on sheet 34
MEB3_GPMC_A11: U83.8(A10) ; also on sheet 34
MEB3_GPMC_A12: U83.7(A11) ; also on sheet 34
MEB3_GPMC_A13: R394.2 U83.6(A12) ; also on sheet 34
MEB3_GPMC_A14: R396.2 U83.5(A13) ; also on sheet 34
MEB3_GPMC_A15: R397.2 U83.4(A14) ; also on sheet 34
MJB1_QSPI1_RTCLK: R468.2 RJ24.1
MJB3_GPMC_A16: R400.2 U83.3(A15) ; also on sheet 32
MJB3_GPMC_A17: R395.2 U83.54(A16) ; also on sheet 32
MJB3_GPMC_A18: R370.2 U83.19(A17) ; also on sheet 32
MJB3_GPMC_A19: R375.2 U83.18(A18) ; also on sheet 32
MMB3_GPMC_AD00: J40.A9 U83.35(DQ0) ; also on sheet 31 32
MMB3_GPMC_AD01: J40.B8 U83.37(DQ1) ; also on sheet 31 32
MMB3_GPMC_AD02: J40.A8 U83.39(DQ2) ; also on sheet 31 32
MMB3_GPMC_AD03: J40.A7 U83.41(DQ3) ; also on sheet 31 32
MMB3_GPMC_AD04: J40.B6 U83.44(DQ4) ; also on sheet 31 32
MMB3_GPMC_AD05: J40.B5 U83.46(DQ5) ; also on sheet 31 32
MMB3_GPMC_AD06: J40.A6 U83.48(DQ6) ; also on sheet 31 32
MMB3_GPMC_AD07: J40.A5 U83.50(DQ7) ; also on sheet 32
MMB3_GPMC_AD08: J40.A4 U83.36(DQ8) ; also on sheet 31 32
MMB3_GPMC_AD09: J40.B7 U83.38(DQ9) ; also on sheet 31 32
MMB3_GPMC_AD10: J40.A10 U83.40(DQ10) ; also on sheet 31 32
MMB3_GPMC_AD11: J40.B9 U83.42(DQ11) ; also on sheet 31 32
MMB3_GPMC_AD12: J40.B4 U83.45(DQ12) ; also on sheet 31 32
MMB3_GPMC_AD13: J40.B10 U83.47(DQ13) ; also on sheet 31 32
MMB3_GPMC_AD14: J40.B11 U83.49(DQ14) ; also on sheet 31 32
MMB3_GPMC_AD15: J40.A11 RJ25.1 ; also on sheet 31 32
MMB3_GPMC_ADVn_ALE: J40.A14 ; also on sheet 32
MMB3_GPMC_BEN0: J40.B1 ; also on sheet 32
MMB3_GPMC_BEN1: J40.B2 ; also on sheet 32
MMB3_GPMC_CLK: J40.C3 ; also on sheet 32
MMB3_GPMC_CS0: J40.A13 RU82.2(I) ; also on sheet 32
MMB3_GPMC_OEn_REn: J40.D3 R46.1 U83.34(~{OE}) ; also on sheet 32
MMB3_GPMC_WAIT0: J40.B12 R9419.1 ; also on sheet 32
MMB3_GPMC_WEn: J40.C2 R385.1 U83.13(~{WE}) ; also on sheet 32
MUX_CNTL0: RU82.1(OE) U8017.1(P00) ; also on sheet 26 31
MUX_CNTL1: R9211.2 U8017.2(P01) ; also on sheet 26
MUX_CNTL2: R9212.2 U8017.3(P02) ; also on sheet 26
MUX_CNTL3: R9210.2 U8017.4(P03) ; also on sheet 26
MUX_CNTL4: R9208.2 U8017.5(P04) ; also on sheet 26
MUX_CNTL5: R9209.2 U8017.6(P05) ; also on sheet 26
MUX_CNTL6: R9206.2 U8017.7(P06) ; also on sheet 26
MUX_CNTL7: R9205.2 U8017.8(P07) ; also on sheet 26
MUX_CNTL8: R9223.2 U8017.9(P10) ; also on sheet 26
MUX_CNTL9: R9221.2 U8017.10(P11) ; also on sheet 26
MUX_CNTL10: R9222.2 U8017.11(P12) ; also on sheet 26
MUX_CNTL11: R9225.2 U8017.12(P13) ; also on sheet 26
MUX_CNTL12: R9224.2 U8017.13(P14) ; also on sheet 26
MUX_CNTL13: TP8060.1(TP) U8006.24(P27) ; also on sheet 26
NOR_CEn: R364.1 RU82.4(O) U83.32(~{CE})
PCF_VPP_ENn: U44.13(P10) ; also on sheet 31
PG_VTT: R282.1 U64.9(PGOOD)
PMIC_REGEN_DDR: R283.1 TP8068.1(TP) U64.7(EN) ; also on sheet 13 14
POWERHOLD_CLK: TP8059.1(TP) U8006.23(P26) ; also on sheet 14
R_DCAN1_RX/GPIO4_10: R9052.1 ; also on sheet 35
R_DCAN1_TX/GPIO4_9: R9051.1 ; also on sheet 35
R_GPMC_AD00/RGMII1_RXD2/GPIO1_14/SYSBOOT0: R9000.1 ; also on sheet 32
R_GPMC_AD01/RGMII1_RXD1/GPIO1_15/SYSBOOT1: R9001.1 ; also on sheet 32
R_GPMC_AD02/RGMII1_RXD0/GPIO1_16/SYSBOOT2: R9002.1 ; also on sheet 32
R_GPMC_AD03/QSPI1_RTCLK/GPIO1_17/SYSBOOT3: R9003.1 ; also on sheet 32
R_GPMC_AD04/CAM_STROBE/GPIO1_18/SYSBOOT4: R9004.1 ; also on sheet 32
R_GPMC_AD05/UART2_TXD/TIMER6/SPI3_D1/GPIO1_19/SYSBOOT5: R9005.1 ; also on sheet 32
R_GPMC_AD06/UART2_RXD/TIMER5/SPI3_D0/GPIO1_20/SYSBOOT6: R9006.1 ; also on sheet 32
R_GPMC_AD07/CAM_SHUTTER/TIMER4/SPI3_SCLK/GPIO1_21: R9007.1 ; also on sheet 32
R_GPMC_AD08/TIMER7/SPI3_CS0/GPIO1_22/SYSBOOT8: R9008.1 ; also on sheet 32
R_GPMC_AD09/eCAP1_IN_PWM1_OUT/SPI3_CS1/GPIO1_23/SYSBOOT9: R9009.1 ; also on sheet 32
R_GPMC_AD10/TIMER2/GPIO1_24/SYSBOOT10: R9010.1 ; also on sheet 32
R_GPMC_AD11/TIMER3/GPIO1_25/SYSBOOT11: R9011.1 ; also on sheet 32
R_GPMC_AD12/GPIO1_26/SYSBOOT12: R9012.1 ; also on sheet 32
R_GPMC_AD13/RGMII1_RXC/GPIO1_27/SYSBOOT1: R9013.1 ; also on sheet 32
R_GPMC_AD14/SPI2_CS1/GPIO1_28/SYSBOOT14: R9014.1 ; also on sheet 32
R_GPMC_AD15/SPI2_CS0/GPIO1_29/SYSBOOT15: R9015.1 ; also on sheet 32
R_GPMC_ADVn_ALE/RGMII1_TXD2/EHRPWM1_TRIPZONE_INPUT/CLKOUT1/DMA_EVT4/GPIO1_3: R9019.1 ; also on sheet 32
R_GPMC_BEN0/RGMII1_TXCTL/EHRPWM1A/DMA_EVT2/GPIO1_1: R9017.1 ; also on sheet 32
R_GPMC_BEN1/RGMII1_TXD3/EHRPWM1B/DMA_EVT3/GPIO1_2: R9018.1 ; also on sheet 32
R_GPMC_CLK/RGMII1_TXC/CLKOUT0/DMA_EVT1/GPIO1_0: R9016.1 ; also on sheet 32
R_GPMC_CS0/RGMII1_RXCTL/GPIO1_6: R9022.1 ; also on sheet 32
R_GPMC_CS1/QSPI1_CS0/GPIO1_7: R9023.1 ; also on sheet 32
R_GPMC_CS2/QSPI1_D3/GPIO1_8: R9024.1 ; also on sheet 32
R_GPMC_CS3/QSPI1_D2/GPIO1_9: R9025.1 ; also on sheet 32
R_GPMC_CS4/QSPI1_D0/GPIO1_10: R9026.1 ; also on sheet 32
R_GPMC_CS5/QSPI1_D1/GPIO1_11: R9027.1 ; also on sheet 32
R_GPMC_CS6/QSPI1_SCLK/GPIO1_12: R9028.1 ; also on sheet 32
R_GPMC_OEn_REn/RGMII1_TXD1/EHRPWM_SYNCI/CLKOUT2/GPIO1_4: R9020.1 ; also on sheet 32
R_GPMC_WAIT0/RGMII1_RXD3/QSPI1_RTCLK/DMA_EVT4/GPIO1_13: R9029.1 ; also on sheet 32
R_GPMC_WEn/RGMII1_TXD0/EHRPWM_SYNCO/GPIO1_5: R9021.1 ; also on sheet 32
R_I2C1_SCL: R9030.1 R9313.2 RJ5.3 RJ7.1 U44.22(SCL) U8006.29(SCL) U8017.29(SCL) ; also on sheet 13 28 29 36
R_I2C1_SDA: R9031.1 R9314.2 RJ6.3 RJ8.1 U44.23(SDA) U8006.30(SDA) U8017.30(SDA) ; also on sheet 13 28 29 36
R_I2C2_SCL: R9032.1 R9315.2 RJ5.1 RJ7.3 ; also on sheet 29
R_I2C2_SDA: R9033.1 R9316.2 RJ6.1 RJ8.3 ; also on sheet 29
R_MCAN_RX/CAM_nRESET/VIN2A_VSYNC0/SPI1_CS3/UART3_TXD/GPMC_CS7/VIN1B_VSYNC1/GPIO4_12: R9054.1 ; also on sheet 27
R_MDIO_MCLK/SPI4_D1/VIN2A_D0/GPIO3_17: R9055.1 ; also on sheet 34
R_QSPI1_SCLK: R728.1 U18.16(SCLK)
R_RGMII0_RXC/CAM_STROBE/MMC_CLK/VIN2B_D0/GPIO3_25: R9063.1 ; also on sheet 34
R_RGMII0_RXCTL/CAM_SHUTTER/MMC_CMD/VIN2B_D1/GPIO3_26: R9064.1 ; also on sheet 34
R_RGMII0_RXD0/MMC_DAT3/VIN2B_D5/GPIO3_30: R9068.1 ; also on sheet 34
R_RGMII0_RXD1/MMC_DAT2/VIN2B_D4/GPIO3_29: R9067.1 ; also on sheet 34
R_RGMII0_RXD2/MMC_DAT1/VIN2B_D3/GPIO3_28: R9066.1 ; also on sheet 34
R_RGMII0_RXD3/MMC_DAT0/VIN2B_D2/GPIO3_27: R9065.1 ; also on sheet 34
R_RGMII0_TXC/CAM_STROBE/SPI4_SCLK/MMC_CLK/VIN2A_D2/GPIO3_19: R9057.1 ; also on sheet 34
R_RGMII0_TXCTL/CAM_SHUTTER/SPI4_CS0/MMC_CMD/VIN2A_D3/GPIO3_2: R9058.1 ; also on sheet 34
R_RGMII0_TXD0/MMC_DAT3/VIN2A_D7/GPIO3_24: R9062.1 ; also on sheet 34
R_RGMII0_TXD1/MMC_DAT2/VIN2A_D6/GPIO3_23: R9061.1 ; also on sheet 34
R_RGMII0_TXD2/eCAP1_IN_PWM1_OUT/MMC_DAT1/VIN2A_D5/GPIO3_22: R9060.1 ; also on sheet 34
R_RGMII0_TXD3/MMC_DAT0/VIN2A_D4/GPIO3_21: R9059.1 ; also on sheet 34
R_SPI1_CS0/UART3_TXD/GPIO4_3: R9037.1 ; also on sheet 34
R_SPI1_CS1/SPI3_CS1/TIMER6/EHRPWM1_TRIPZONE_INPUT/GPIO4_4: R9038.1 ; also on sheet 34
R_SPI1_D0/UART3_RTSn/GPIO4_2: R9036.1 ; also on sheet 34
R_SPI1_D1/UART3_CTSn/GPIO4_1: R9035.1 ; also on sheet 34
R_SPI1_SCLK/UART3_RXD/GPIO4_0: R9034.1 ; also on sheet 34
R_SPI2_CS0/UART3_TXD/EHRPWM1B/TIMER4/GPIO4_8: R9042.1 ; also on sheet 35 36
R_SPI2_D1/UART3_CTSn/TIMER5/eCAP1_IN_PWM_OUT/GPIO4_6: R9040.1 ; also on sheet 35 36
R_SPI2_SCLK/UART3_RXD/EHRPWM1A/TIMER3/GPIO4_5: R9039.1 ; also on sheet 35 36
R_UART1_CTSn/XREF_CLK1/UART3_RXD/GPMC_A16/SPI4_SCLK/SPI1_CS2/TIMER3/EHRPWM1_SYNCI: R9045.1 ; also on sheet 32
R_UART1_RTSn/UART3_TXD/GPMC_A17/SPI4_CS0/SPI1_CS3/TIMER4/EHRPWM1_SYNCO: RJ24.3 ; also on sheet 32
R_UART1_RXD/SPI4_D1/QSPI1_RTCLK/GPMC_A12/GPMC_A12/DCAN2_TX/GPIO4_13: R9046.1 ; also on sheet 32
R_UART1_TXD/SPI4_D0/GPMC_A13/GPMC_A13/DCAN2_RX/GPIO4_1: R9044.1 ; also on sheet 32
R_UART2_CTSn/XREF_CLK1/GPMC_A18/SPI3_SCLK/QSPI_CS1/TIMER7/VIN2B_D6/VIN2A_HSYNC0/GPMC_CLK: R9049.1 ; also on sheet 32
R_UART2_RXD/SPI3_D1/QSPI1_RTCLK/GPMC_A12/TIMER1/EHRPWM1A/GPMC_CLK/GPMC_A12/DCAN1_TX/GPIO4_17: R9047.1 ; also on sheet 32
R_UART2_TXD/SPI3_D0/TIMER2/EHRPWM1B/GPMC_A13/DCAN1_RX/GPIO4_18: R9048.1 ; also on sheet 32
R_VIN1A_CLK0/CPI_PCLK/CLKOUT0/GPIO1_30: R9069.1 ; also on sheet 34
R_VIN1A_D00/CPI_DATA2/GPIO2_3: R9074.1 ; also on sheet 34
R_VIN1A_D01/CPI_DATA3/GPIO2_4: R9075.1 ; also on sheet 34
R_VIN1A_D02/CPI_DATA4/GPIO2_5: R9076.1 ; also on sheet 34
R_VIN1A_D03/CPI_DATA5/GPIO2_6: R9077.1 ; also on sheet 34
R_VIN1A_D04/CPI_DATA6/GPIO2_7: R9078.1 ; also on sheet 34
R_VIN1A_D05/CPI_DATA7/GPIO2_8: R9079.1 ; also on sheet 34
R_VIN1A_D06/CPI_DATA8/GPIO2_9: R9080.1 ; also on sheet 34
R_VIN1A_D07/CPI_DATA9/GPIO2_10: R9081.1 ; also on sheet 34
R_VIN1A_D08/CPI_DATA10/VIN1B_D0/GPMC_A8/SYS_NIRQ2/GPIO2_11: R9082.1 ; also on sheet 34
R_VIN1A_D09/CPI_DATA11/VIN1B_D1/GPMC_A9/SYS_NIRQ1/GPIO2_12: R9083.1 ; also on sheet 34
R_VIN1A_D10/CPI_DATA12/VIN1B_D2/GPMC_A10/SYS_NIRQ2/GPIO2_13: R9084.1 ; also on sheet 34
R_VIN1A_D11/CPI_DATA13/VIN1B_D3/GPMC_A11/SYS_NIRQ1/GPIO2_14: R9085.1 ; also on sheet 34
R_VIN1A_D12/CPI_DATA14/VIN1B_D4/GPMC_A12/DMA_EVT1/GPIO2_15: R9086.1 ; also on sheet 34
R_VIN1A_D13/CPI_WEn/VIN1B_D5/GPMC_A13/DMA_EVT2/GPIO2_16: R9087.1 ; also on sheet 34
R_VIN1A_D14/CPI_FID/VIN1B_D6/GPMC_A14/MCASP1_AXR14/GPIO2_17: R9088.1 ; also on sheet 34
R_VIN1A_D15/CPI_DATA15/VIN1B_D7/GPMC_A15/MCASP1_AXR15/GPIO2_18: R9089.1 ; also on sheet 34
R_VIN1A_DE0/CPI_HSYNC/VIN1B_CLK1/CLKOUT1/GPIO1_31: R9070.1 ; also on sheet 34
R_VIN1A_FLD0/CPI_VSYNC/VIN2B_CLK1/CLKOUT2/GPIO2_0: R9071.1 ; also on sheet 34
R_VIN1A_HSYNC0/CPI_DATA0/VIN1A_DE0/GPIO2_1: R9072.1 ; also on sheet 34
R_VIN1A_VSYNC0/CPI_DATA1/GPIO2_2: R9073.1 ; also on sheet 34
R_VIN2A_CLK0/GPIO2_19: R9090.1 ; also on sheet 32
R_VIN2A_DE0/CAM_STROBE/VIN2B_HSYNC1/VIN2B_DE1/GPIO4_21: R9091.1 ; also on sheet 34
R_VIN2A_FLD0/CAM_SHUTTER/VIN2B_VSYNC1/GPIO4_22: R9092.1 ; also on sheet 34
R_VOUT1_CLK/VIN1A_D12/CLKOUT0/VIN2A_CLK0/GPIO2_20: R9117.1 ; also on sheet 30
R_VOUT1_D00/MCASP1_AXR0/VIN1A_D17/MMC_CLK/GPIO2_25: R9093.1 ; also on sheet 30
R_VOUT1_D01/MCASP1_AXR1/VIN1A_D18/MMC_CMD/GPIO2_26: R9094.1 ; also on sheet 30
R_VOUT1_D02/MCASP1_AXR2/VIN1A_D19/MCASP1_AXR8/MMC_DAT0/OBS0/OBS16/OBS_IRQ1/GPIO2_27: R9095.1 ; also on sheet 30
R_VOUT1_D03/MCASP1_AXR3/VIN1A_D20/MCASP1_AXR9/MMC_DAT1/OBS1/OBS17/OBS_DMARQ1/GPIO2_28: R9096.1 ; also on sheet 30
R_VOUT1_D04/MCASP1_AXR4/VIN1A_D21/MCASP1_AXR10/MMC_DAT2/OBS2/OBS18/GPIO2_29: R9097.1 ; also on sheet 30
R_VOUT1_D05/MCASP1_AXR5/VIN1A_D22/MCASP1_AXR11/MMC_DAT3/OBS3/OBS19/VIN2A_CLK0/GPIO2_30: R9098.1 ; also on sheet 30
R_VOUT1_D06/MCASP1_AXR6/VIN1A_D23/MCASP1_AXR12/ESM_ERROR/OBS4/OBS20/VIN2A_DE0/GPIO2_31: R9099.1 ; also on sheet 30 31
R_VOUT1_D07/MCASP1_AXR7/eCAP1_IN_PWM1_OUT/MCASP1_AXR13/EMU3/VIN2A_FLD0/GPIO3_0: R9100.1 ; also on sheet 30 31
R_VOUT1_D08/MCASP1_AXR8/VIN2A_D0/GPMC_A20/EMU4/GPIO3_1: R9101.1 ; also on sheet 30 31
R_VOUT1_D09/MCASP1_AXR9/VIN2A_D1/GPMC_A21/EMU5/GPIO3_2: R9102.1 ; also on sheet 30 31
R_VOUT1_D10/MCASP1_AXR10/VIN2A_D2/GPMC_A22/EMU6/OBS5/OBS21/OBS_IRQ2/GPIO3_3: R9103.1 ; also on sheet 30 31
R_VOUT1_D11/MCASP1_AXR11/VIN2A_D3/GPMC_A23/EMU7/OBS6/OBS22/OBS_DMARQ2/GPIO3_: R9104.1 ; also on sheet 30 31
R_VOUT1_D12/MCASP1_AXR12/VIN2A_D4/GPMC_A24/EMU8/OBS7/OBS23/GPIO3_5: R9105.1 ; also on sheet 30 31
R_VOUT1_D13/MCASP1_AXR13/VIN2A_D5/GPMC_A25/EMU9/OBS8/OBS24/GPIO3_6: R9106.1 ; also on sheet 30 31
R_VOUT1_D14/MCASP1_AXR14/VIN2A_D6/GPMC_A26/EMU10/OBS9/OBS25/GPIO3_7: R9107.1 ; also on sheet 30 31
R_VOUT1_D15/MCASP1_AXR15/VIN2A_D7/GPMC_A27/EMU11/OBS10/OBS26/GPIO3_: R9108.1 ; also on sheet 30 31
R_VOUT1_D16/MCASP1_AHCLKX/VIN2A_D8/GPMC_A0/MCASP1_ARX8/VIN2B_D0/EMU12/GPIO3_9: R9109.1 ; also on sheet 30 31
R_VOUT1_D17/VIN2A_D9/GPMC_A1/MCASP1_ARX9/VIN2B_D1/EMU13/GPIO3_10: R9110.1 ; also on sheet 30 31
R_VOUT1_D18/VIN2A_D10/GPMC_A2/MCASP1_AXR10/VIN2B_D2/EMU14/OBS11/OBS27/GPIO3_1: R9111.1 ; also on sheet 30 31
R_VOUT1_D19/VIN2A_D11/GPMC_A3/MCASP1_AXR11/VIN2B_D3/EMU15/OBS12/OBS28/GPIO3_12: R9112.1 ; also on sheet 30 31
R_VOUT1_D20/VIN2A_D12/GPMC_A4/MCASP1_AXR12/VIN2B_D4/EMU16/OBS13/OBS29/GPIO3_13: R9113.1 ; also on sheet 30 31
R_VOUT1_D21/VIN2A_D13/GPMC_A5/MCASP1_AXR13/VIN2B_D5/EMU17/OBS14/OBS30/GPIO3_14: R9114.1 ; also on sheet 30 31
R_VOUT1_D22/VIN2A_D14/GPMC_A6/MCASP1_AXR14/VIN2B_D6/EMU18/OBS15/OBS31/GPIO3_15: R9115.1 ; also on sheet 30 31
R_VOUT1_D23/VIN2A_D15/GPMC_A7/MCASP1_AXR15/VIN2B_D7/EMU19/GPIO3_16: R9116.1 ; also on sheet 30 31
R_VOUT1_DE/MCASP1_ACLKX/VIN1A_D13/CLKOUT1/GPIO2_21: R9118.1 ; also on sheet 30
R_VOUT1_FLD/MCASP1_FSX/VIN1A_D14/CLKOUT2/GPIO2_22: R9119.1 R9318.2 ; also on sheet 26
R_VOUT1_HSYNC/MCASP1_ACLKR//VIN1A_D15/VIN2A_DE0/GPIO2_23: R9120.1 ; also on sheet 30
R_VOUT1_VSYNC/MCASP1_FSR//VIN1A_D16/VIN2A_FLD0/GPIO2_24: R9121.1 ; also on sheet 30
RNB1_QSPI1_CS0: R131.2 U18.7(~{CS}) ; also on sheet 32
RNB1_QSPI1_D0: U18.15(SI/IO0) ; also on sheet 32
RNB1_QSPI1_D1: U18.8(SO/IO1) ; also on sheet 32
RNB1_QSPI1_D2: R442.2 U18.9(~{WP}/IO2) ; also on sheet 32
RNB1_QSPI1_D3: R128.1 U18.1(~{HOLD}/IO3) ; also on sheet 32
RNB1_QSPI1_SCLK: R468.1 R728.2 ; also on sheet 32
RNB2_GPMC_CS1: J40.C1 ; also on sheet 32
RNB2_GPMC_CS2: J40.A15 ; also on sheet 32
RNB2_GPMC_CS3: J40.D2 ; also on sheet 32
RNB2_GPMC_CS4: J40.B14 ; also on sheet 32
RNB2_GPMC_CS5: J40.A12 ; also on sheet 32
RNB2_GPMC_CS6: J40.A3 ; also on sheet 32
RSTOUTn: J40.E14 U18.3(~{RESET}/RFU) U44.3(~{RESET}) U83.14(~{RESET}) U8006.28(~{RESET}) U8017.28(~{RESET}) ; also on sheet 4 22 26
SEL_HDMI_INn: U44.4(P00) ; also on sheet 23 25 31
SPI2_D0/UART3_RTSn/TIMER1/GPIO4_7/SYSBOOT7: R9041.1 ; also on sheet 31 35 36
TS_LCD_GPIO1: U44.20(P17) ; also on sheet 16
TS_LCD_GPIO2: U44.19(P16) ; also on sheet 16
TS_LCD_GPIO3: U44.18(P15) ; also on sheet 16
TS_LCD_GPIO4: U44.17(P14) ; also on sheet 16
VO_VTT: C188.2 C192.2 C202.2 C658.2 R290.2 R9368.1 U64.3(VO)
VOUT_I2C_SCL: RJ7.2 ; also on sheet 16 17 31
VOUT_I2C_SDA: RJ8.2 ; also on sheet 16 17 31
VOUT_MAP0: R9226.2 U8017.14(P15) ; also on sheet 26
VOUT_MAP1: R9228.2 U8017.15(P16) ; also on sheet 26
VOUT_MAP2: R9227.2 U8017.16(P17) ; also on sheet 26
VPRH_1V8: R283.2 ; also on sheet 14 15 16 20 21 22
VPRH_3V3: C67.1 C251.1 C8152.1 U18.2(VCC) U44.24(VCCP) U83.43(VCC) ; also on sheet 11 15 16 17 18 19 20 21 22 23 25 30 31 32 34 35
VPRH_12V0: J1003.1 J1003.2 J1003.3 J1003.4 J1003.6 ; also on sheet 21 37
VPRH_DV: C23.1 C241.1 C293.1 C8048.1 C8049.1 C8087.1 C8088.1 C8151.1 J40.C17 J40.C18 J40.C19 J40.D16 J40.D17 J40.D18 J40.D19 J40.E1 J40.E2 J40.E3 J40.E4 J40.E5 J40.E16 J40.E17 J40.E18 J40.E19 R46.2 R128.2 R131.1 R364.2 R376.1 R379.1 R385.2 R391.1 R442.1 R674.1 R676.1 R677.1 R682.1 R9142.2 R9313.1 R9314.1 R9315.1 R9316.1 R9317.1 R9318.1 R9319.1 RU82.5(VCC) U18.14(VIO/RFU) U44.2(VCCI) U83.29(VIO) U8006.27(VCCP) U8006.31(VCCI) U8017.26(ADDR) U8017.27(VCCP) U8017.31(VCCI) ; also on sheet 4 10 11 13 15 16 17 18 19 20 21 22 23 26 27 28 31 35 36
VSYS_3V3: C174.2 R282.2 U64.10(VIN) ; also on sheet 12 13 14 16 26 27 32 37
ZQ_B01: R5007.1 U5001.L8(ZQ)
ZQ_B4: R5025.1 U5003.H8(ZQ)
ZQ_B23: R5008.1 U5002.L8(ZQ)
N24624886: C5134.1 R5020.1 R5022.1
N27775205: C186.2 R291.2 R292.1 U64.1(REFIN)
N27775249: C179.2 R290.1 U64.5(VOSNS)
N27834162: R376.2 R9419.2 U83.17(RY/~{BY})
N27864606: J40.E20 TP8035.1(TP)
N27864612: J40.D20 TP8036.1(TP)
N28042943: RJ25.2 U83.51(DQ15/A-1)
N30961230: DS4.2(ANODE) R682.2
N30961231: DS2.2(ANODE) R676.2
N30961232: DS3.2(ANODE) R677.2
N30961233: DS1.2(ANODE) R674.2

Not connected (* = marked no-connect by the designer): J28 3 4 9 14 15 19 20 21 22 27 33 39 45 51 56 57 62 63 68 69 74 75 78 80 81 83 84 86 87 92 93 98 99 104 105 106 111* 117; J40 A1 A2 A16 B3 B13 B15 B16 C4 C5 C6 C8 C9 C10 C11 C12 C13 C14 C15 C16* D1 E6 E7 E8 E9 E10 E11 E12; J1003 8 9 14 15 20 21 26 27 32 33 38 39 44 45 50 51 56 57 62 63 68 69 74 75 80 81 86 87 92 93 98 99 104 105 106 110* 111* 116 117; U18 4(DNU.4) 5(DNU.5) 6(RFU.6) 11(DNU.11) 12(DNU.12) 13(NC.13); U44 15(P12); U83 27(NC1)* 28(NC2)* 30(NC3)*; U5001 J1(NC.J1) J9(NC.J9) L1(NC.L1) L9(NC.L9); U5002 J1(NC.J1) J9(NC.J9) L1(NC.L1) L9(NC.L9); U5003 A3(NC.1) A7(~{TDQS}) F1(NC.2) F9(NC.3) H1(NC.4) H9(NC.5)

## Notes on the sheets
sheet 6
- DDR3L Memory
- ECC Option
- Note:  See Data Manual/PCB Guidelines for DDR3 implementation requirements.
- DDR3L Termination and Regulator
- Note:  Enabled pulled to VPRH_1V8 to
  prevent glitch during power-up.
- ER50
- ER23
sheet 8
- Peripheral I/O Control
- (PU_3V3)
- (PU_3V3)
- (PU_3V3)
- (PU_3V3)
- (PU)
- (PU_3V3)
- THESE I/O  GO TO/FROM 3.3V
  CAMERAS AND DISPLAY
  ELEMENTS.
- (PU_3V3)
- ER43
- (PU_3V3)
- [DCAN1_STB]
- (PU_3V3)
- (PD_3V3)
- (PU_3V3)
- (PU)
- (PD)
- (NP-PU/PD)
- (PU-SWPD)
- I/O Expander #1
- I2C Address: 0x20
- [USR_LED1]
- [USR_LED2]
- [USR_LED3]
- [USR_LED4]
- [VIP_RSTn]
- [VOUT_RSTn]
- (PU)
- (PU)
- [TMP102_ALERT]
- (PU)
- [ETH0_RSTn]
- [ETH1_EXP_RSTn]
- (PU)
- (PU)
- [ETH0_EXP_RSTn]
- (PU)
- [SD_CARD_DETECTn]
- (PU)
- [USR_SW1]
- [USR_SW2]
- (PU/PD)
- (PU/PD)
- [USR_SW3]
- (PU/PD)
- [USR_SW4]
- (PU/PD)
- [USR_SW5]
- (PU/PD)
- I/O Expander #2
- I2C Address: 0x22
- ER51
- Note: Mux selection population options for default select.
  Over-rides CPLD internal PullUps.  (Value = 1K)
- Board/CPLD Mux Configuration
- [BRD_MUX_SEL_P00]
- (CPLD-PU)
- [BRD_MUX_SEL_P01]
- (CPLD-PU)
- [BRD_MUX_SEL_P02]
- (CPLD-PU)
- [BRD_MUX_SEL_P03]
- [BRD_MUX_SEL_P04]
- (CPLD-PU)
- (CPLD-PU)
- [BRD_MUX_SEL_P05]
- (CPLD-PU)
- [BRD_MUX_SEL_P06]
- (CPLD-PU)
- [BRD_MUX_SEL_P07]
- (CPLD-PU)
- [BRD_MUX_SEL_P10]
- [BRD_MUX_SEL_P11]
- (CPLD-PU)
- (CPLD-PU)
- [BRD_MUX_SEL_P12]
- (CPLD-PU)
- [BRD_MUX_SEL_P13]
- (CPLD-PU)
- [Unused]
- (CPLD-PU)
- [VOUT_SEL_P15]
- (CPLD-PU)
- [VOUT_SEL_P16]
- (CPLD-PU)
- [VOUT_SEL_P17]
- (CPLD-PU)
- [CAM_SEL_P20]
- (CPLD-PU)
- [CAM_SEL_P21]
- (CPLD-PU)
- [CAM_SEL_P22]
- (CPLD-PU)
- [VIN1_SEL_P23]
- (CPLD-PU)
- [VIN1_SEL_P24]
- [VIN1_SEL_P25]
- (CPLD-PU)
- (CPLD-PU)
- [VIN2_SEL_P26]
- (CPLD-PU)
- [VIN1_SEL_P27]
- (CPLD-PU)
- I/O Expander #3
- I2C Address: 0x23
sheet 9
- Note:  GPMC A1 maps to memory
  A0 because 16b device.
- GPMC Expansion
- MERITEC SOCKET 980020-56-P2
- Note:  DIP Switch used to select on-board memory.
- QSPI Memory
- Note:  DIP Switch used to select on-board memory.
- Note:  See Data Manual/PCB Guidelines for
  RTCLK implementation.
- Values selected via simulation so that
  R_QSIP1_SCLK would be monotonic.
- ROUTE THE FOLLOWING SIGNALS AS A GROUP
  WITH A NET LENGTH LESS THEN 2.75
  INCHES(450ps) AND 60ps OF SKEW.  PLACE THE
  DUAL RESISTOR CLOSE TOGETHER NEAR THE PIN
  OF THE FLASH.
- QSPI1_SCLK
  QSPI1_RTCLK
  QSPI1_CS[0]
  QSPI1_D[0]
  QSPI1_D[1]
  QSPI1_D[2]
  QSPI1_D[3]
- S25FL256SAGMFV001
  MT25QL01GBBB8ESF-0SIT
- ER49
